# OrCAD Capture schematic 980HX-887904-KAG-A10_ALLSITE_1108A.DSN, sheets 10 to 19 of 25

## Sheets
10 A0001-CONFIG: size A2
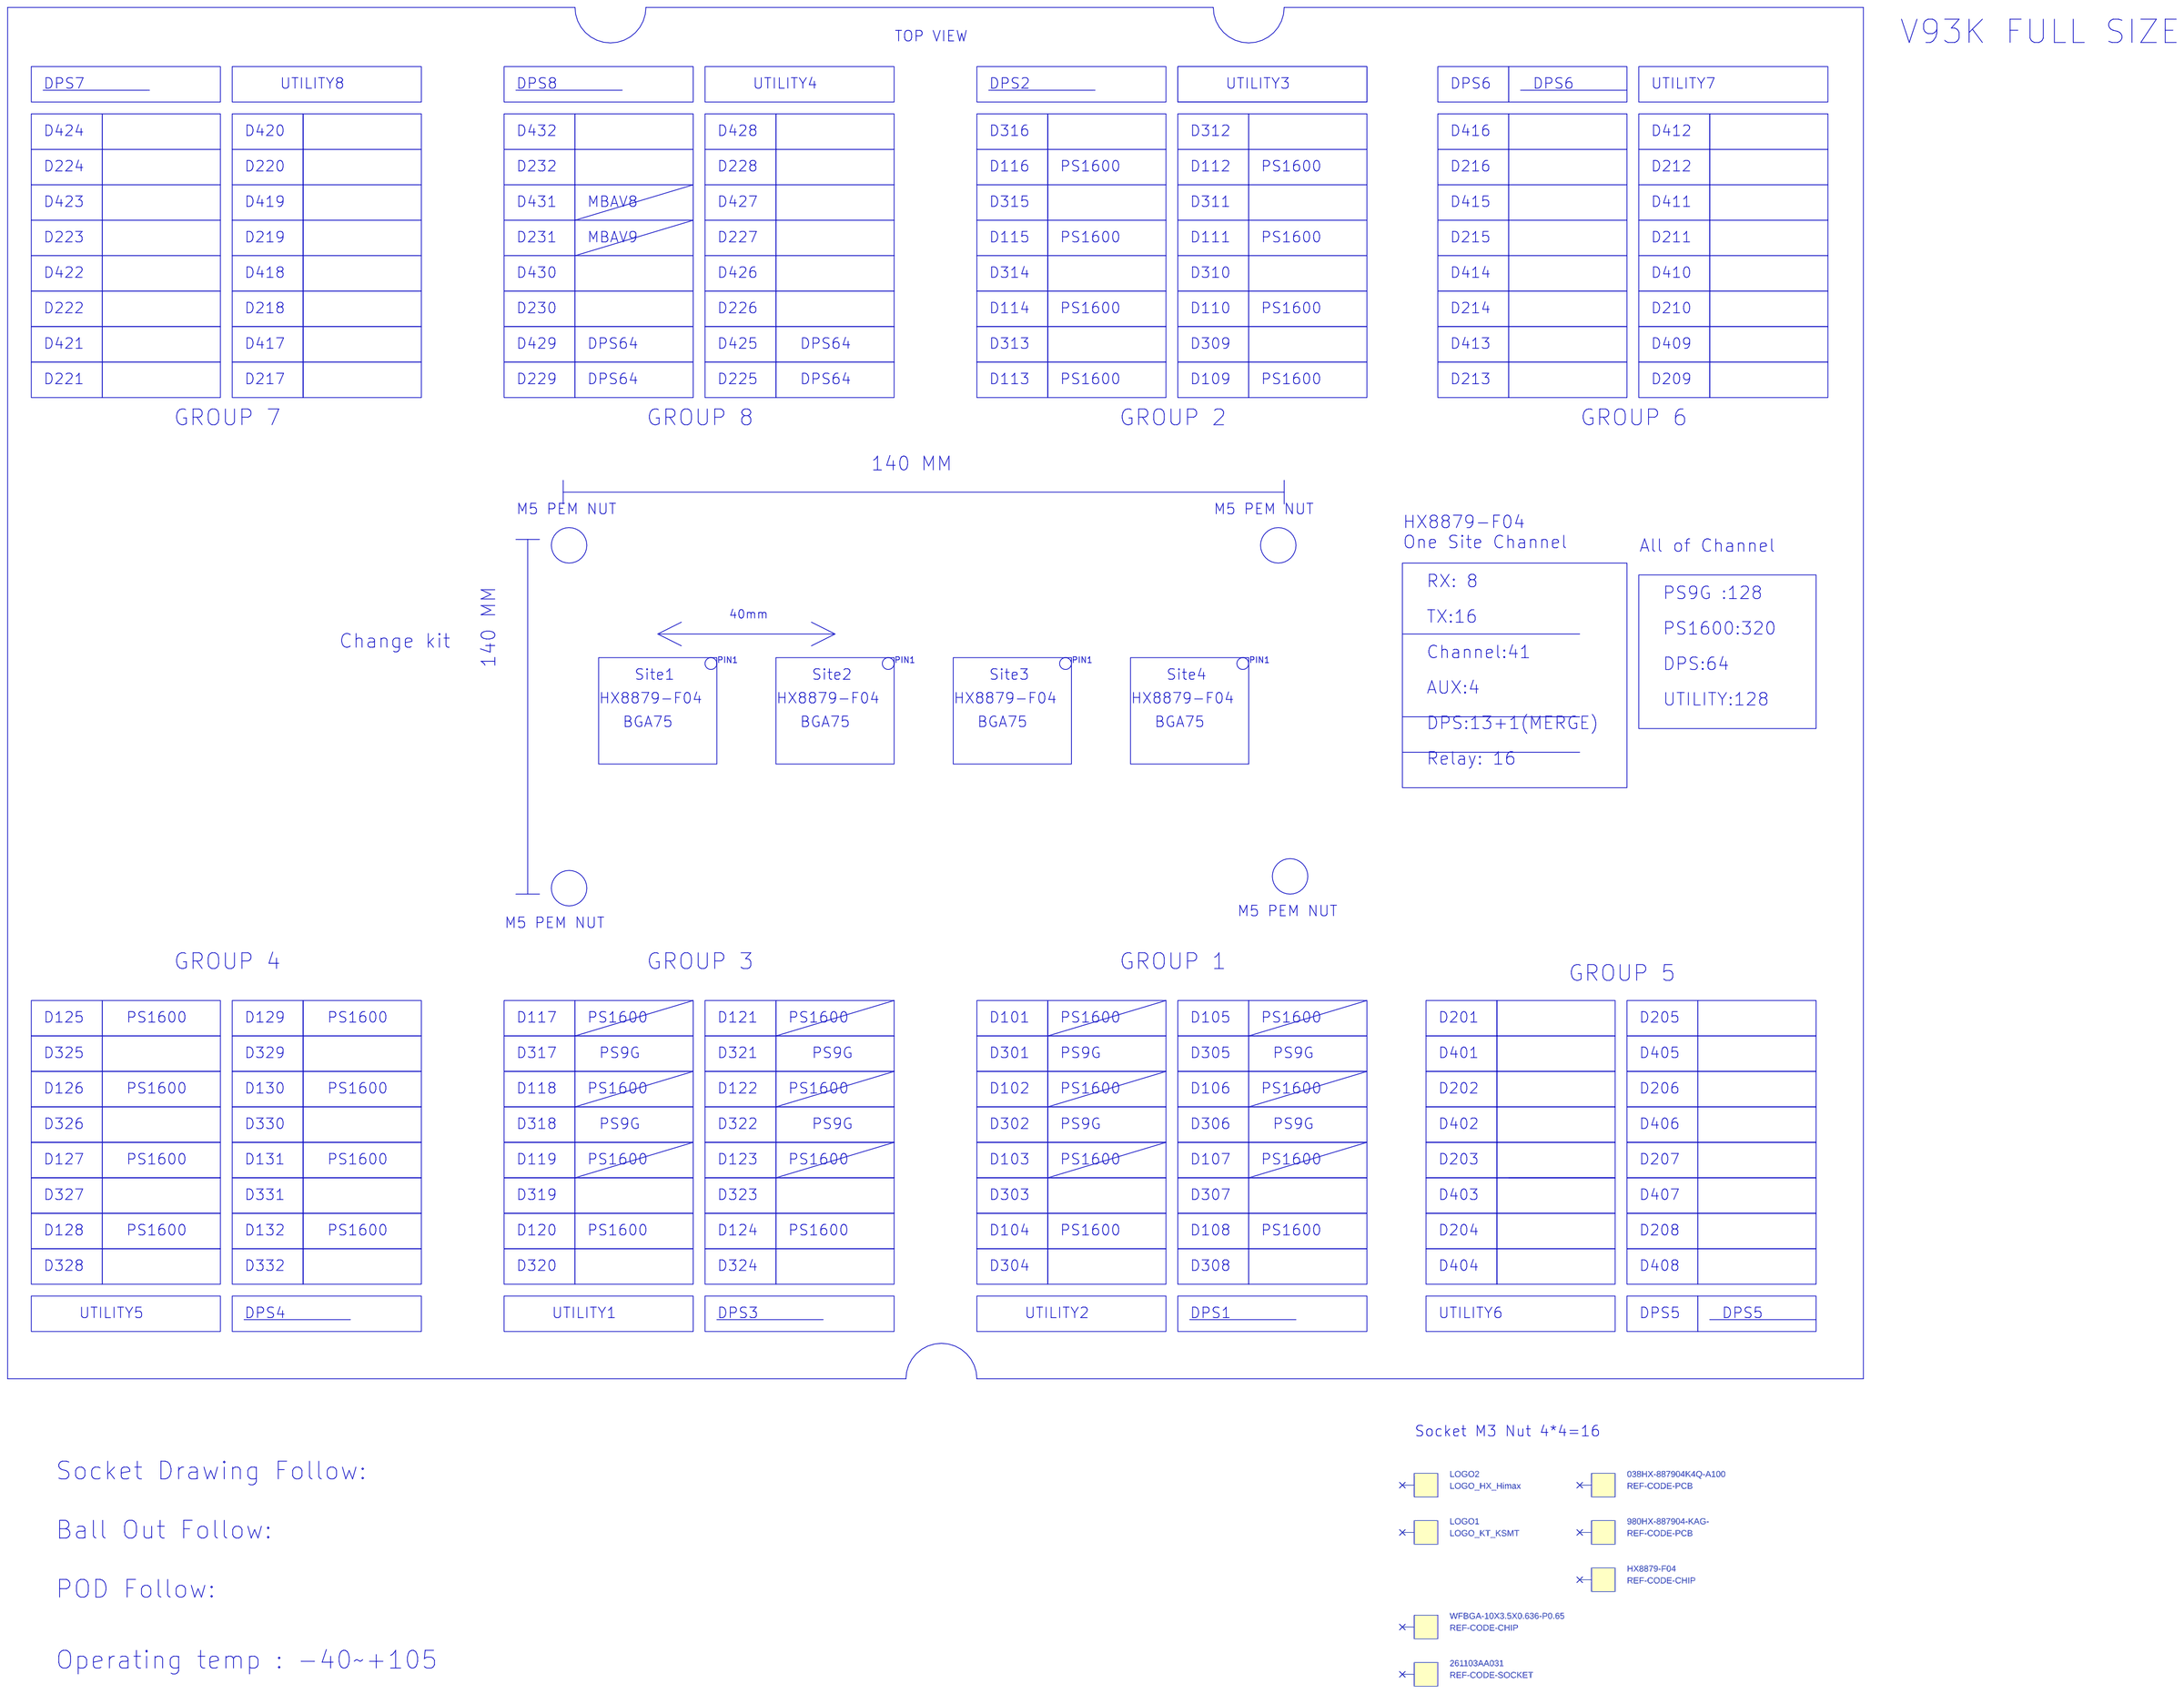
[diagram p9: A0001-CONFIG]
11 A0002-HISTORY
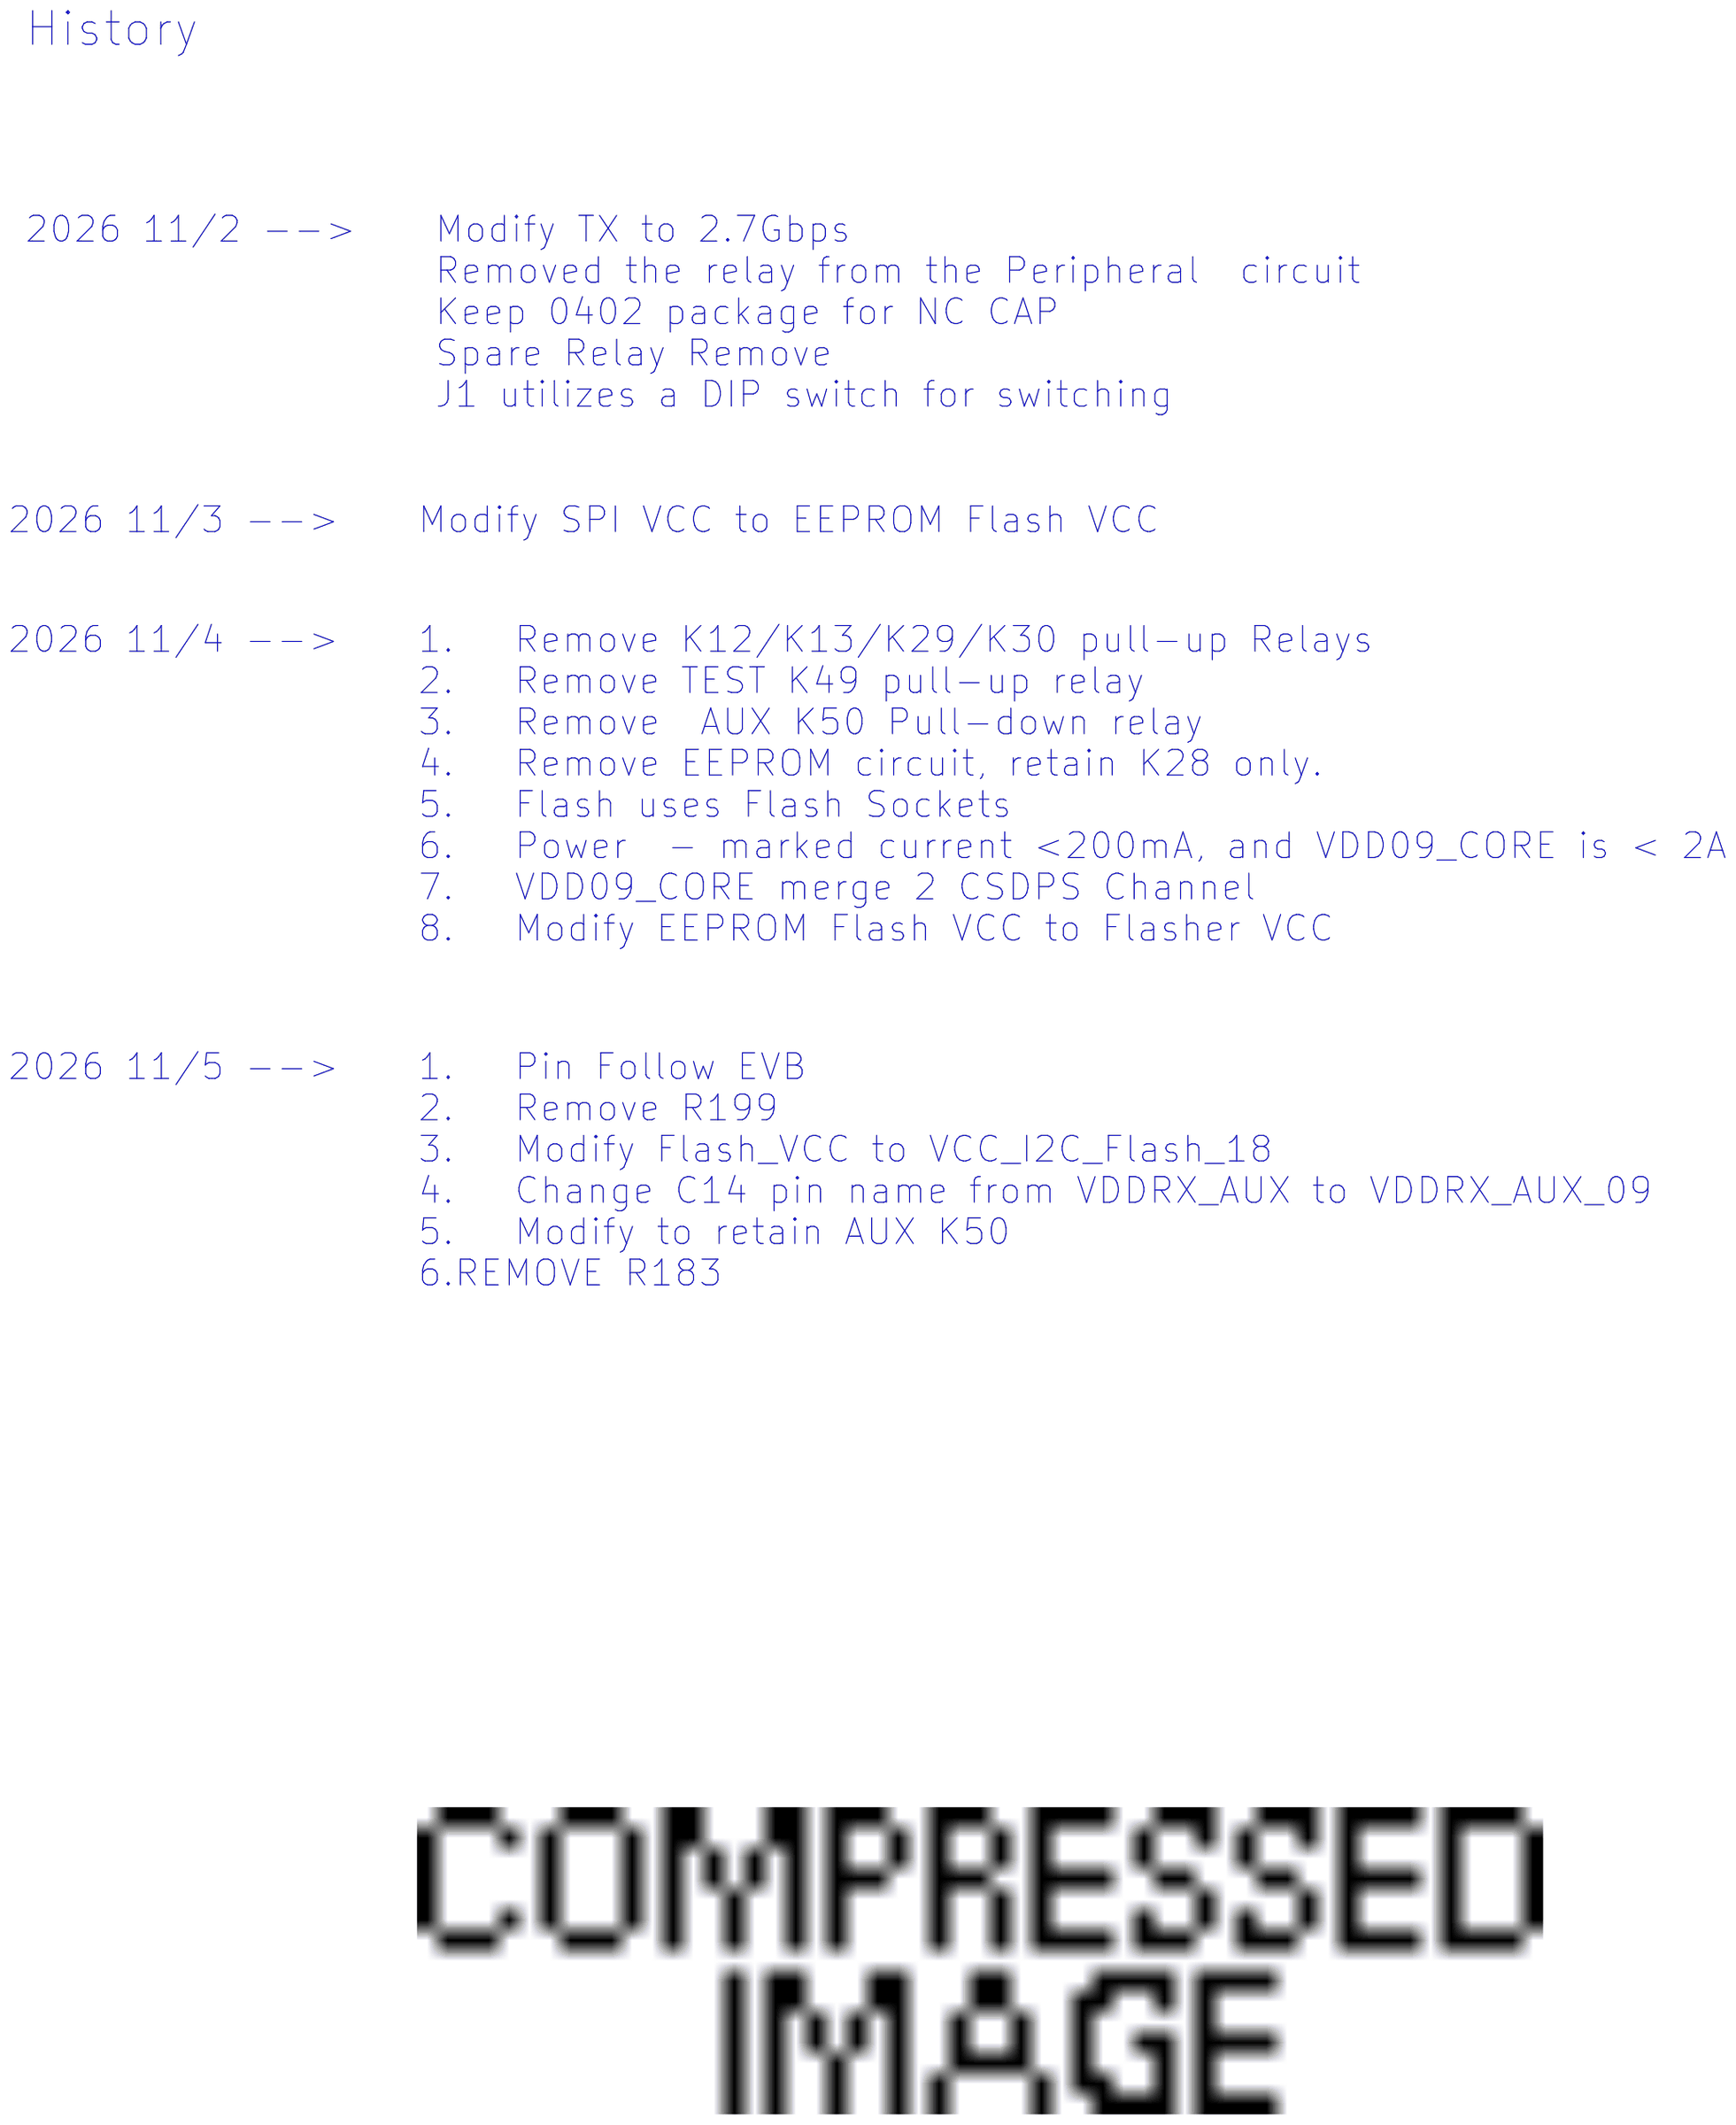
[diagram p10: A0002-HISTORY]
12 P0011_S1_DUT: size A2
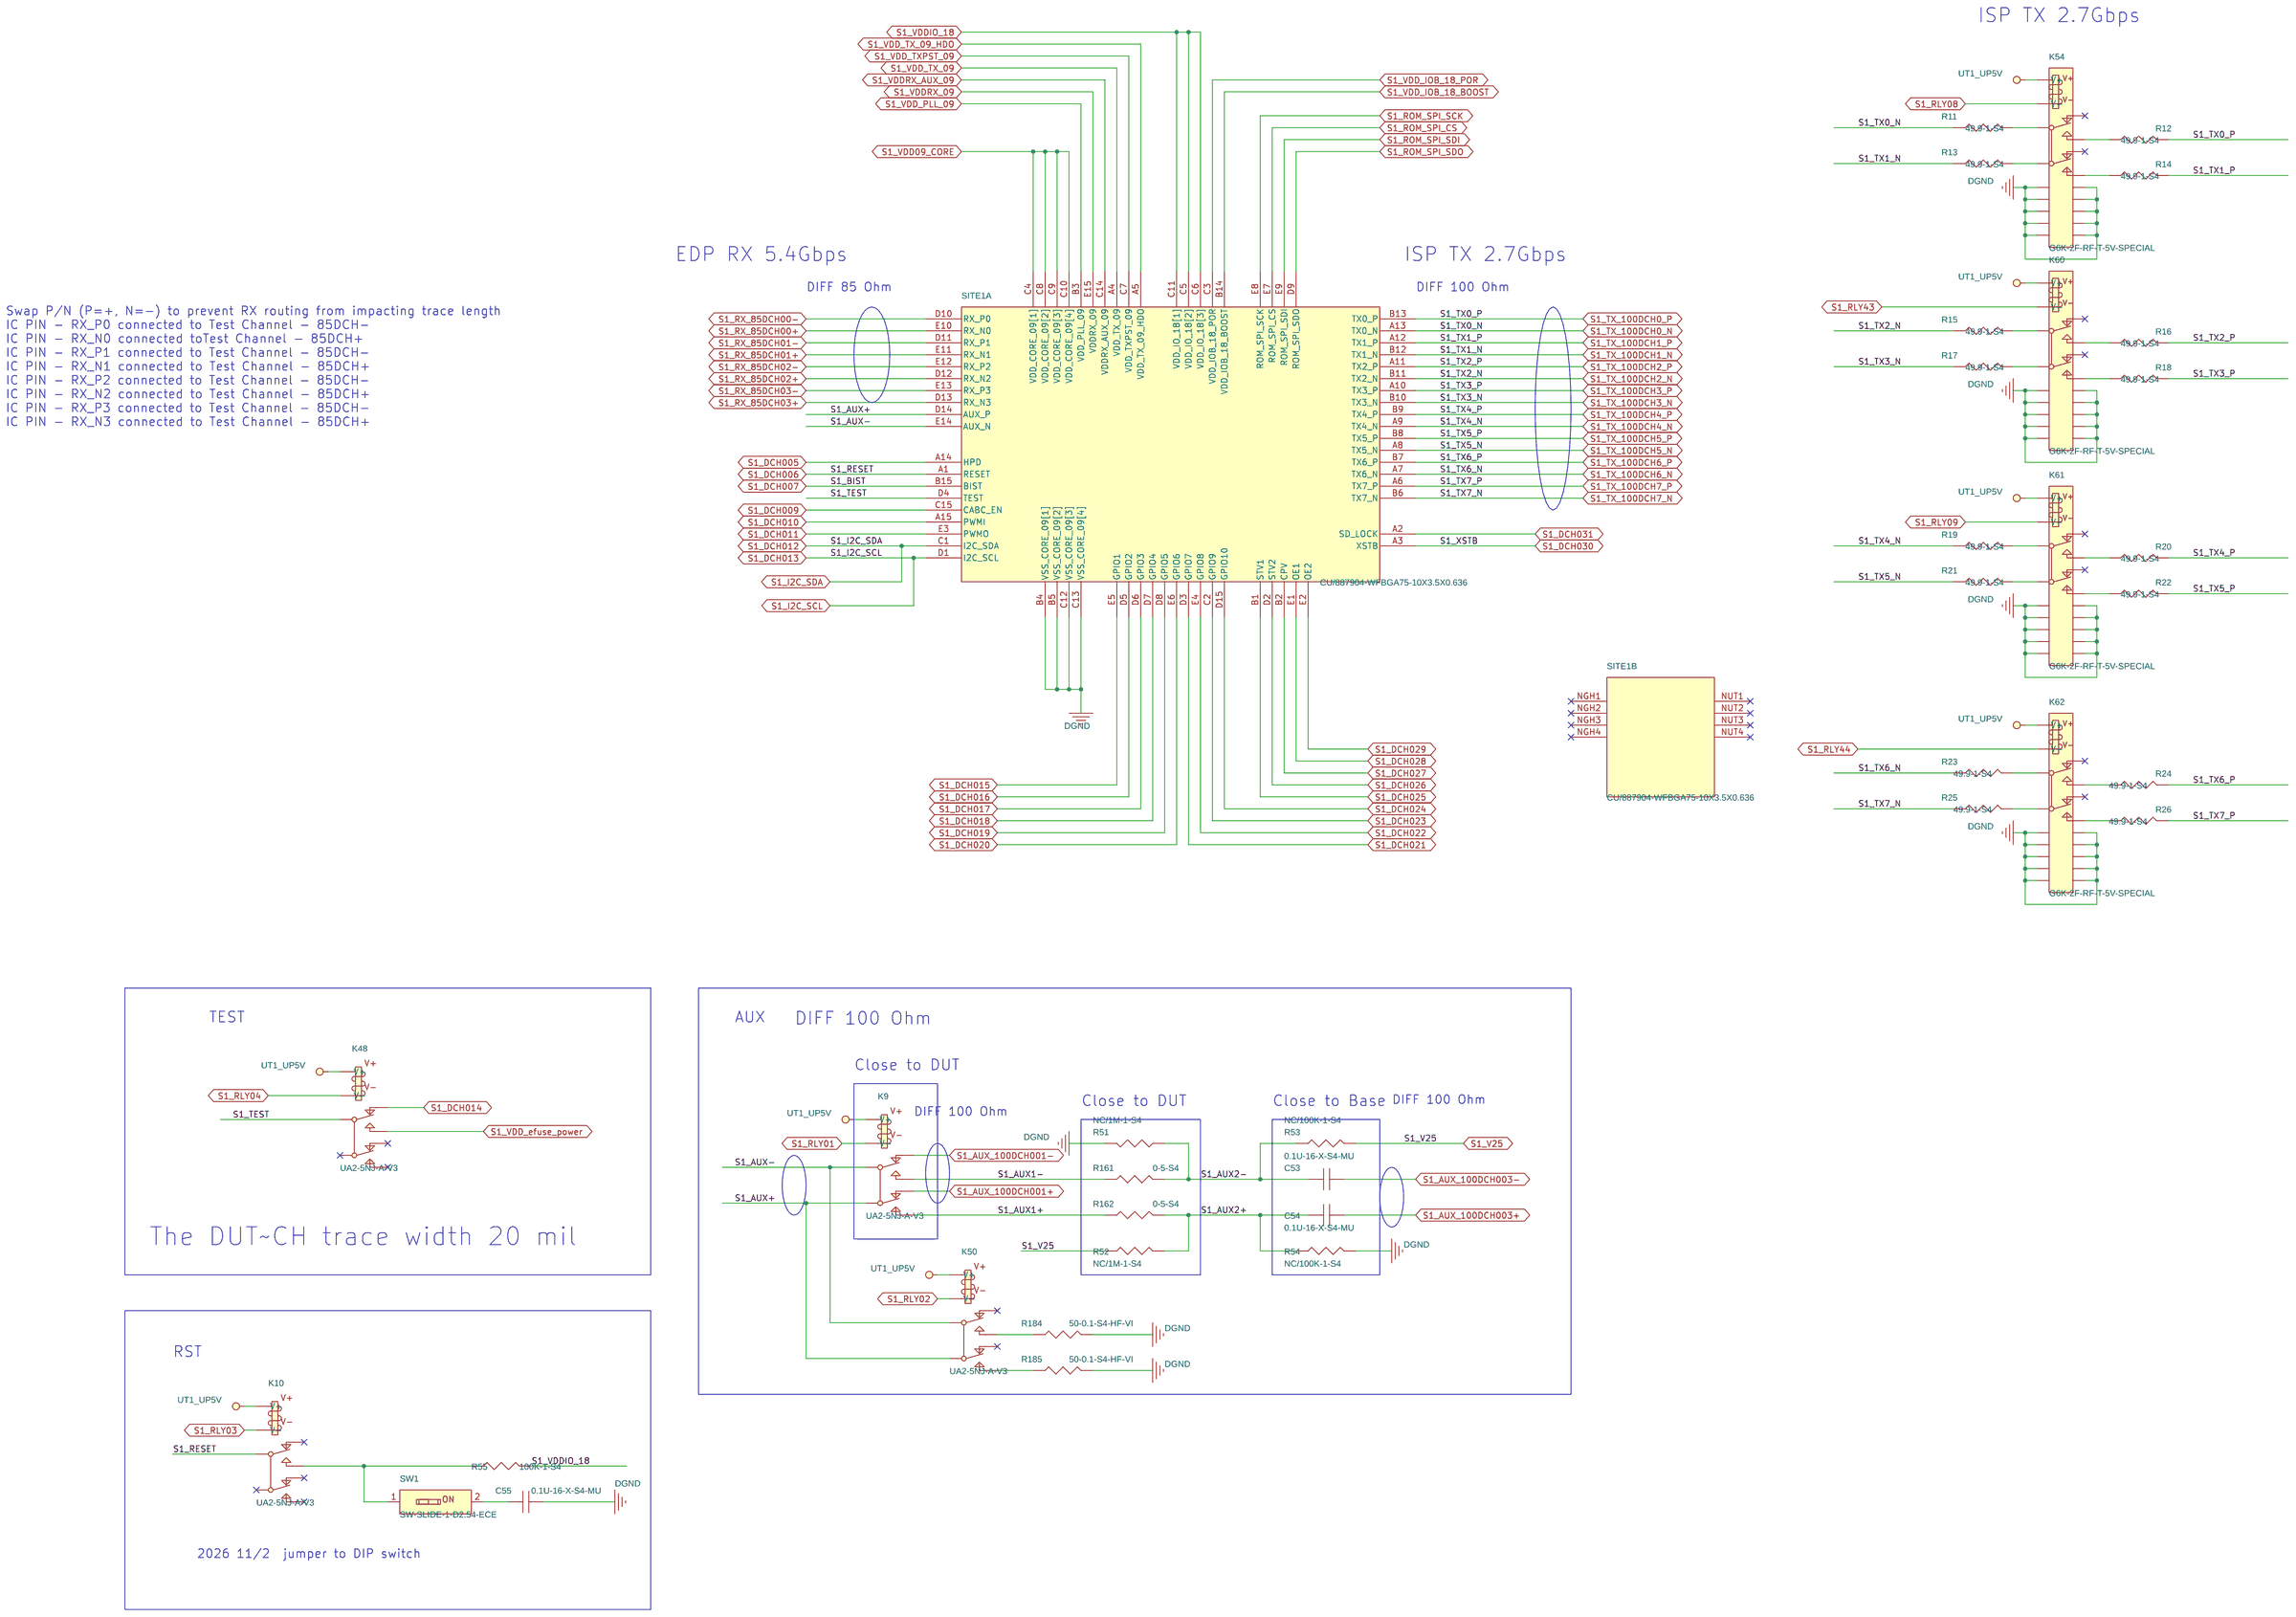
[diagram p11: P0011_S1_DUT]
13 P0012_S1_FLASH_I2C: size A4
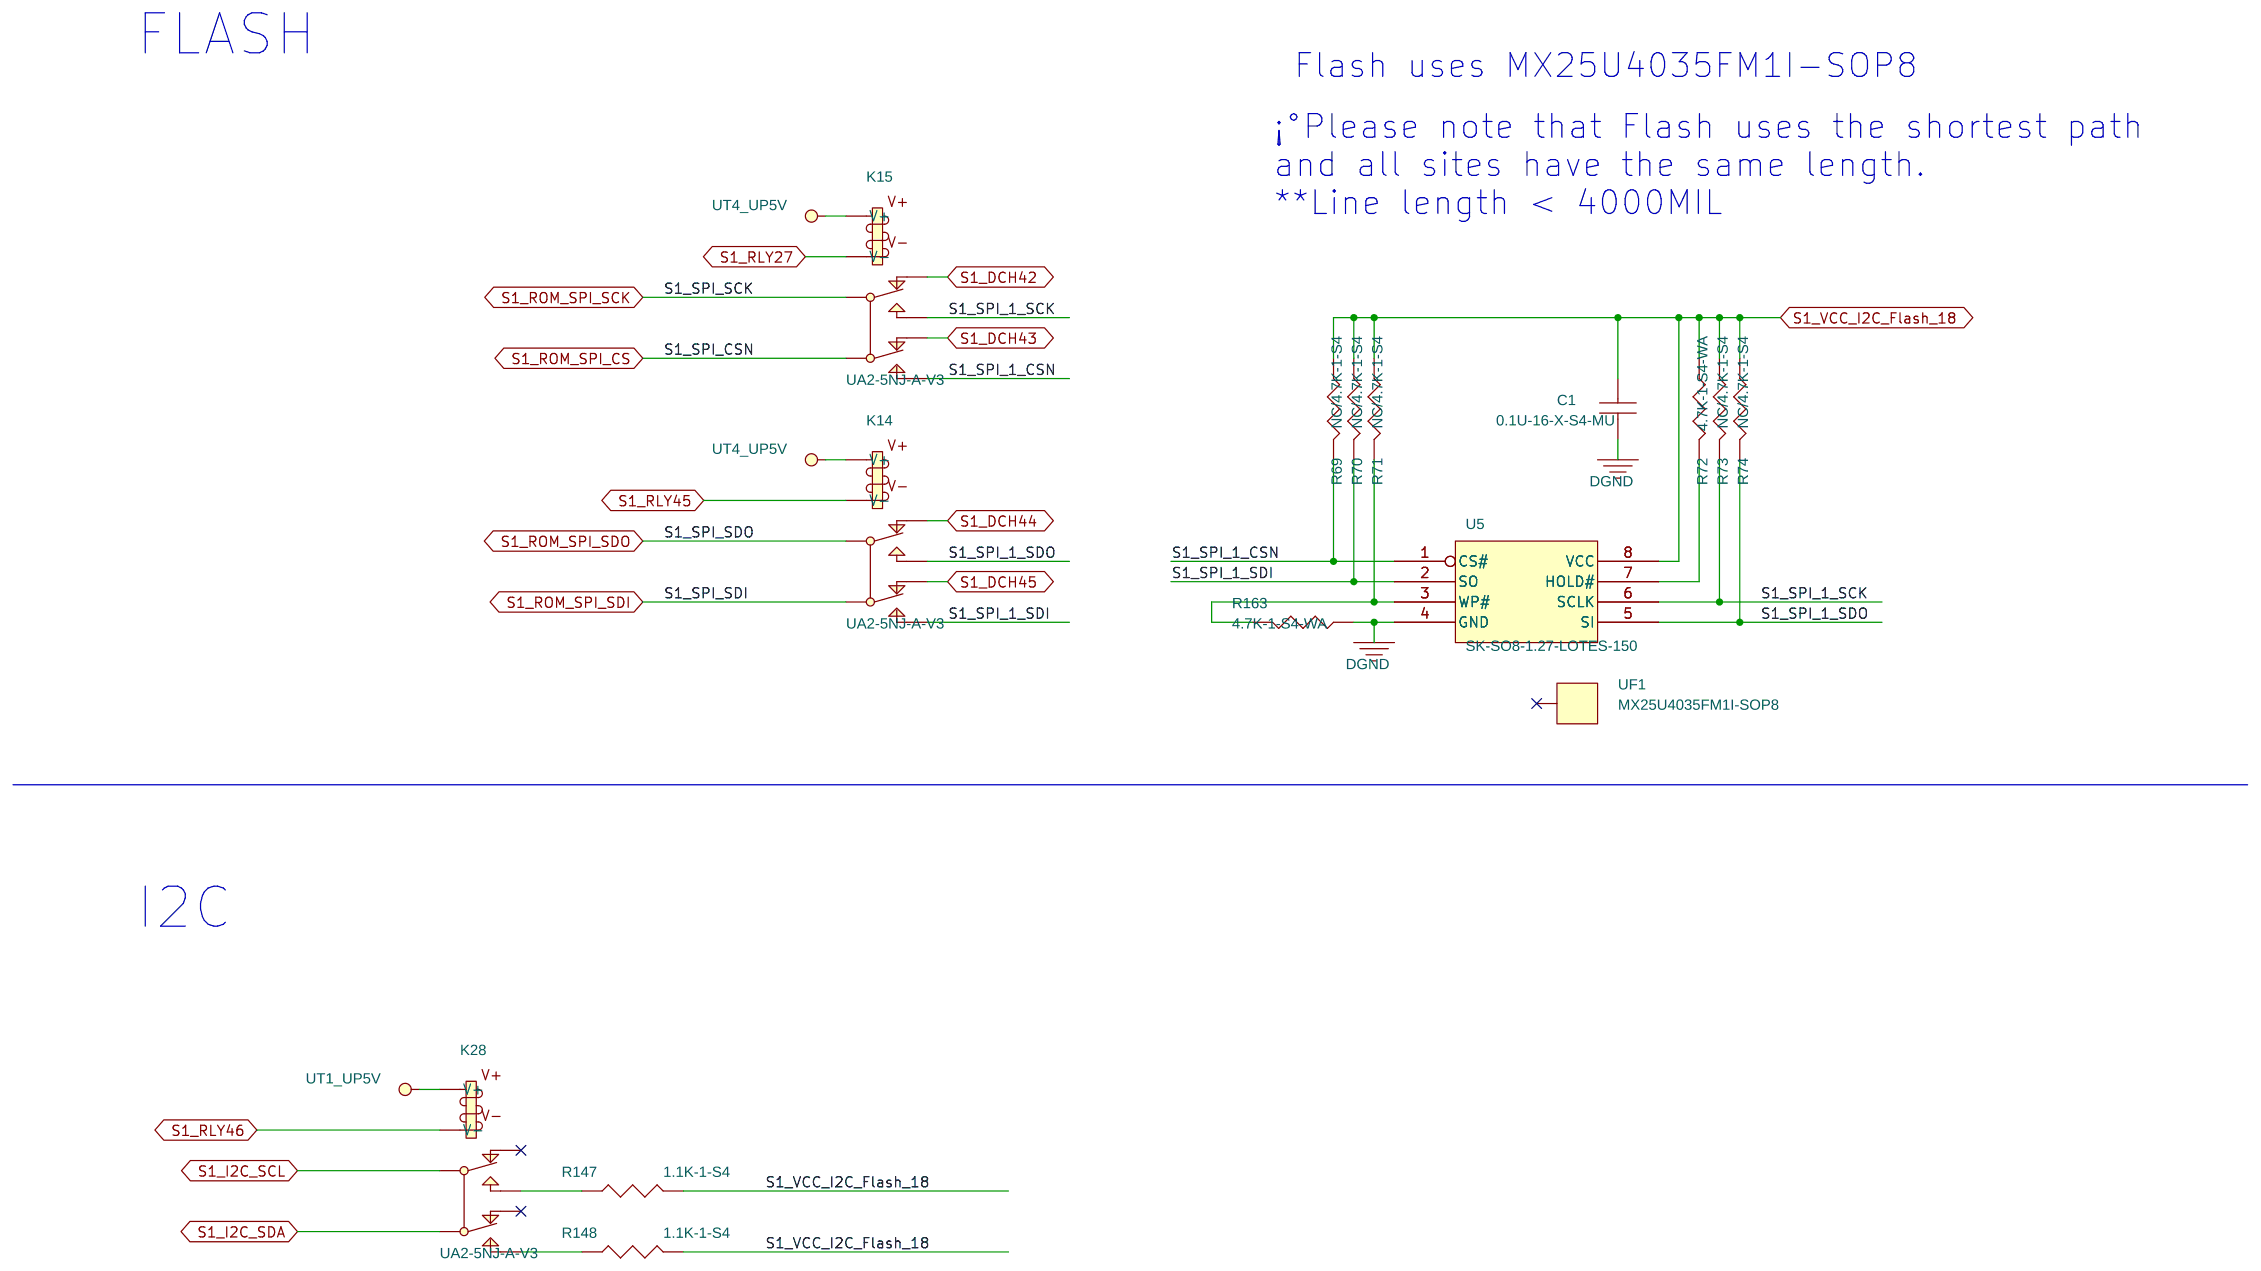
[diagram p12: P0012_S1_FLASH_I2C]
14 P0013_S1_POWER: size A2
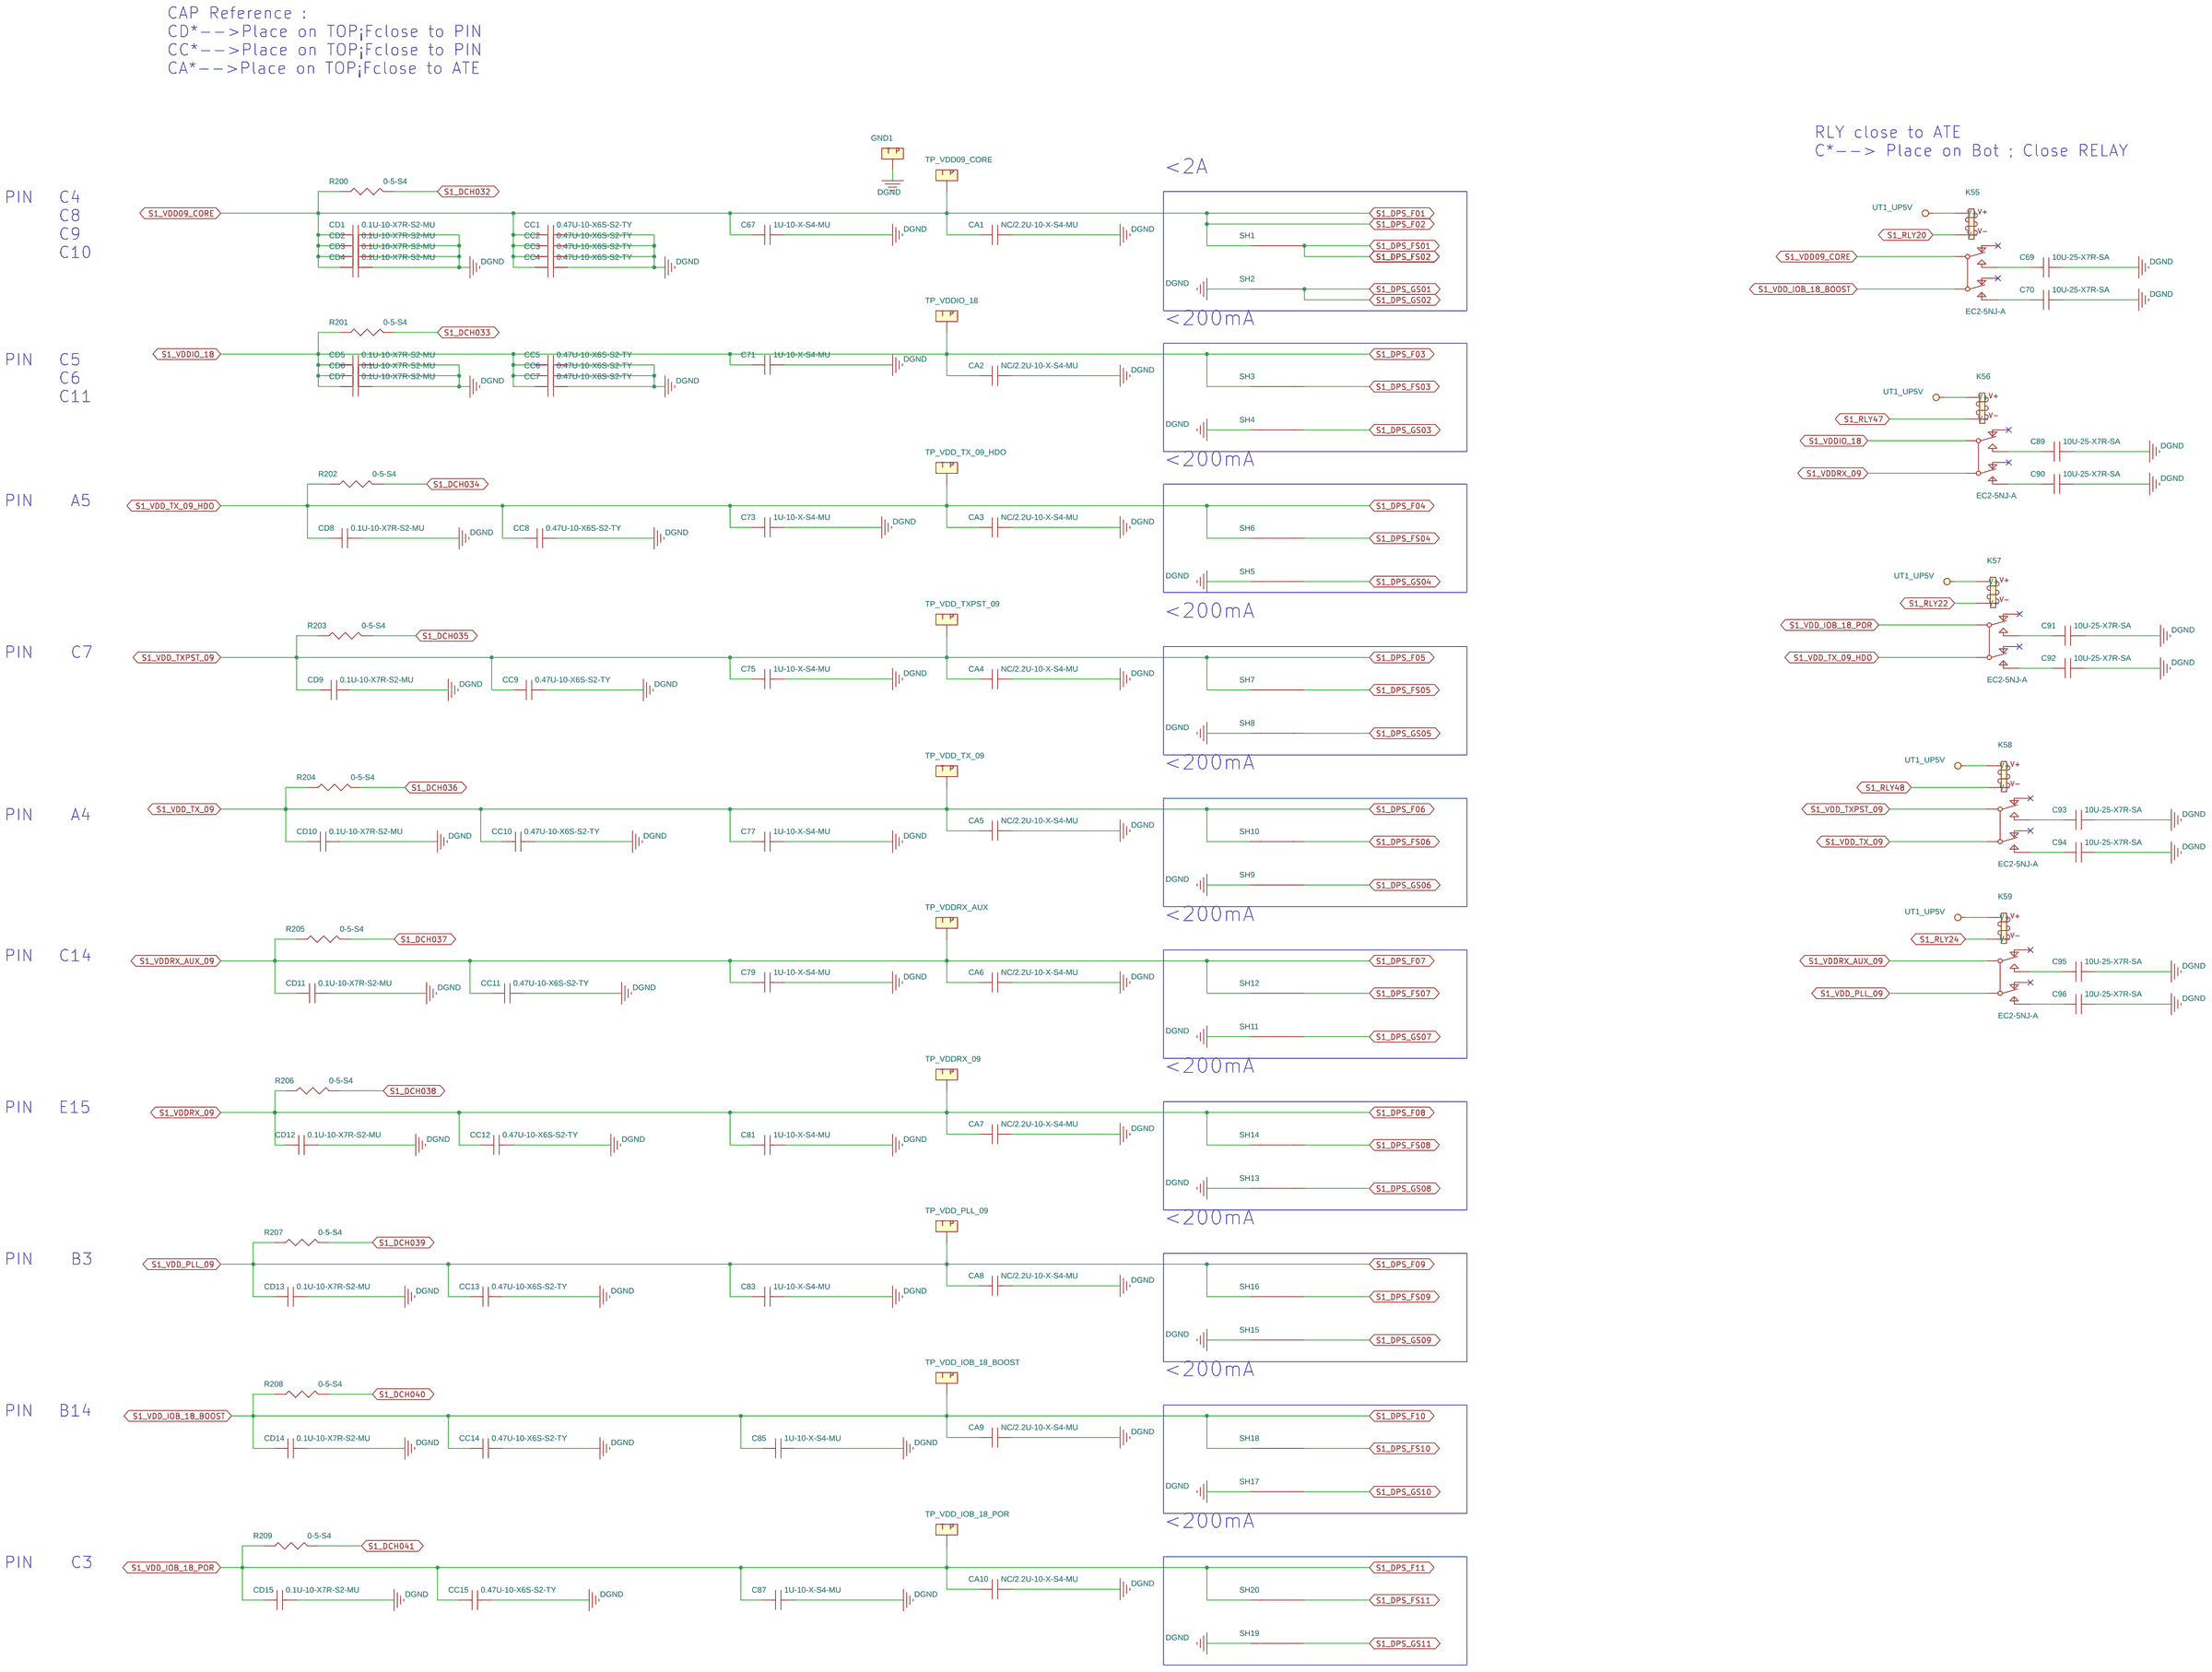
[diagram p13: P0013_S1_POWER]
15 P0014-S1_PWR-OUT: size A4
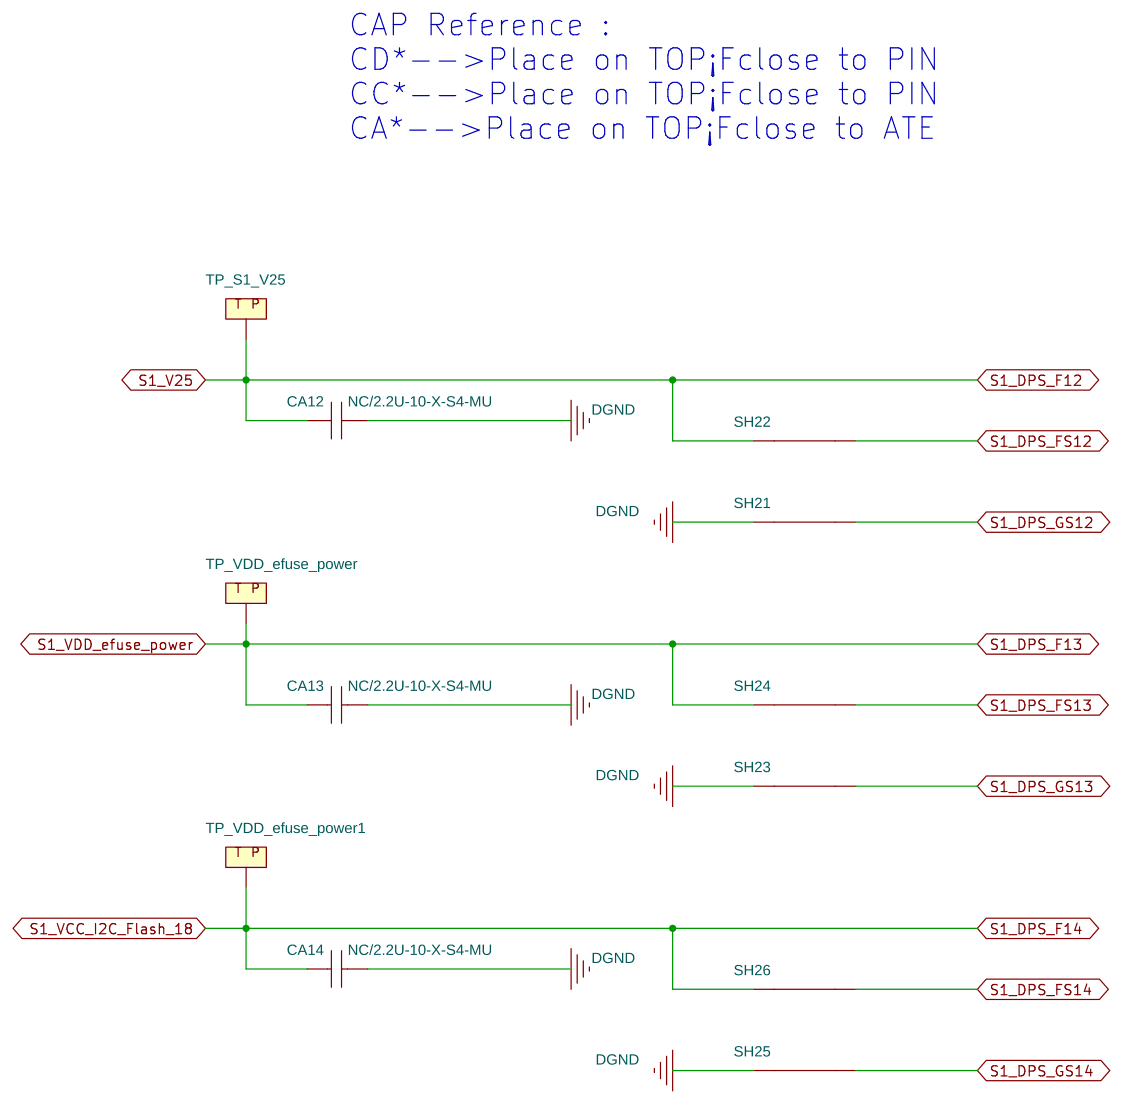
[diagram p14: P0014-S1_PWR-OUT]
16 S9999_MISC: size A3
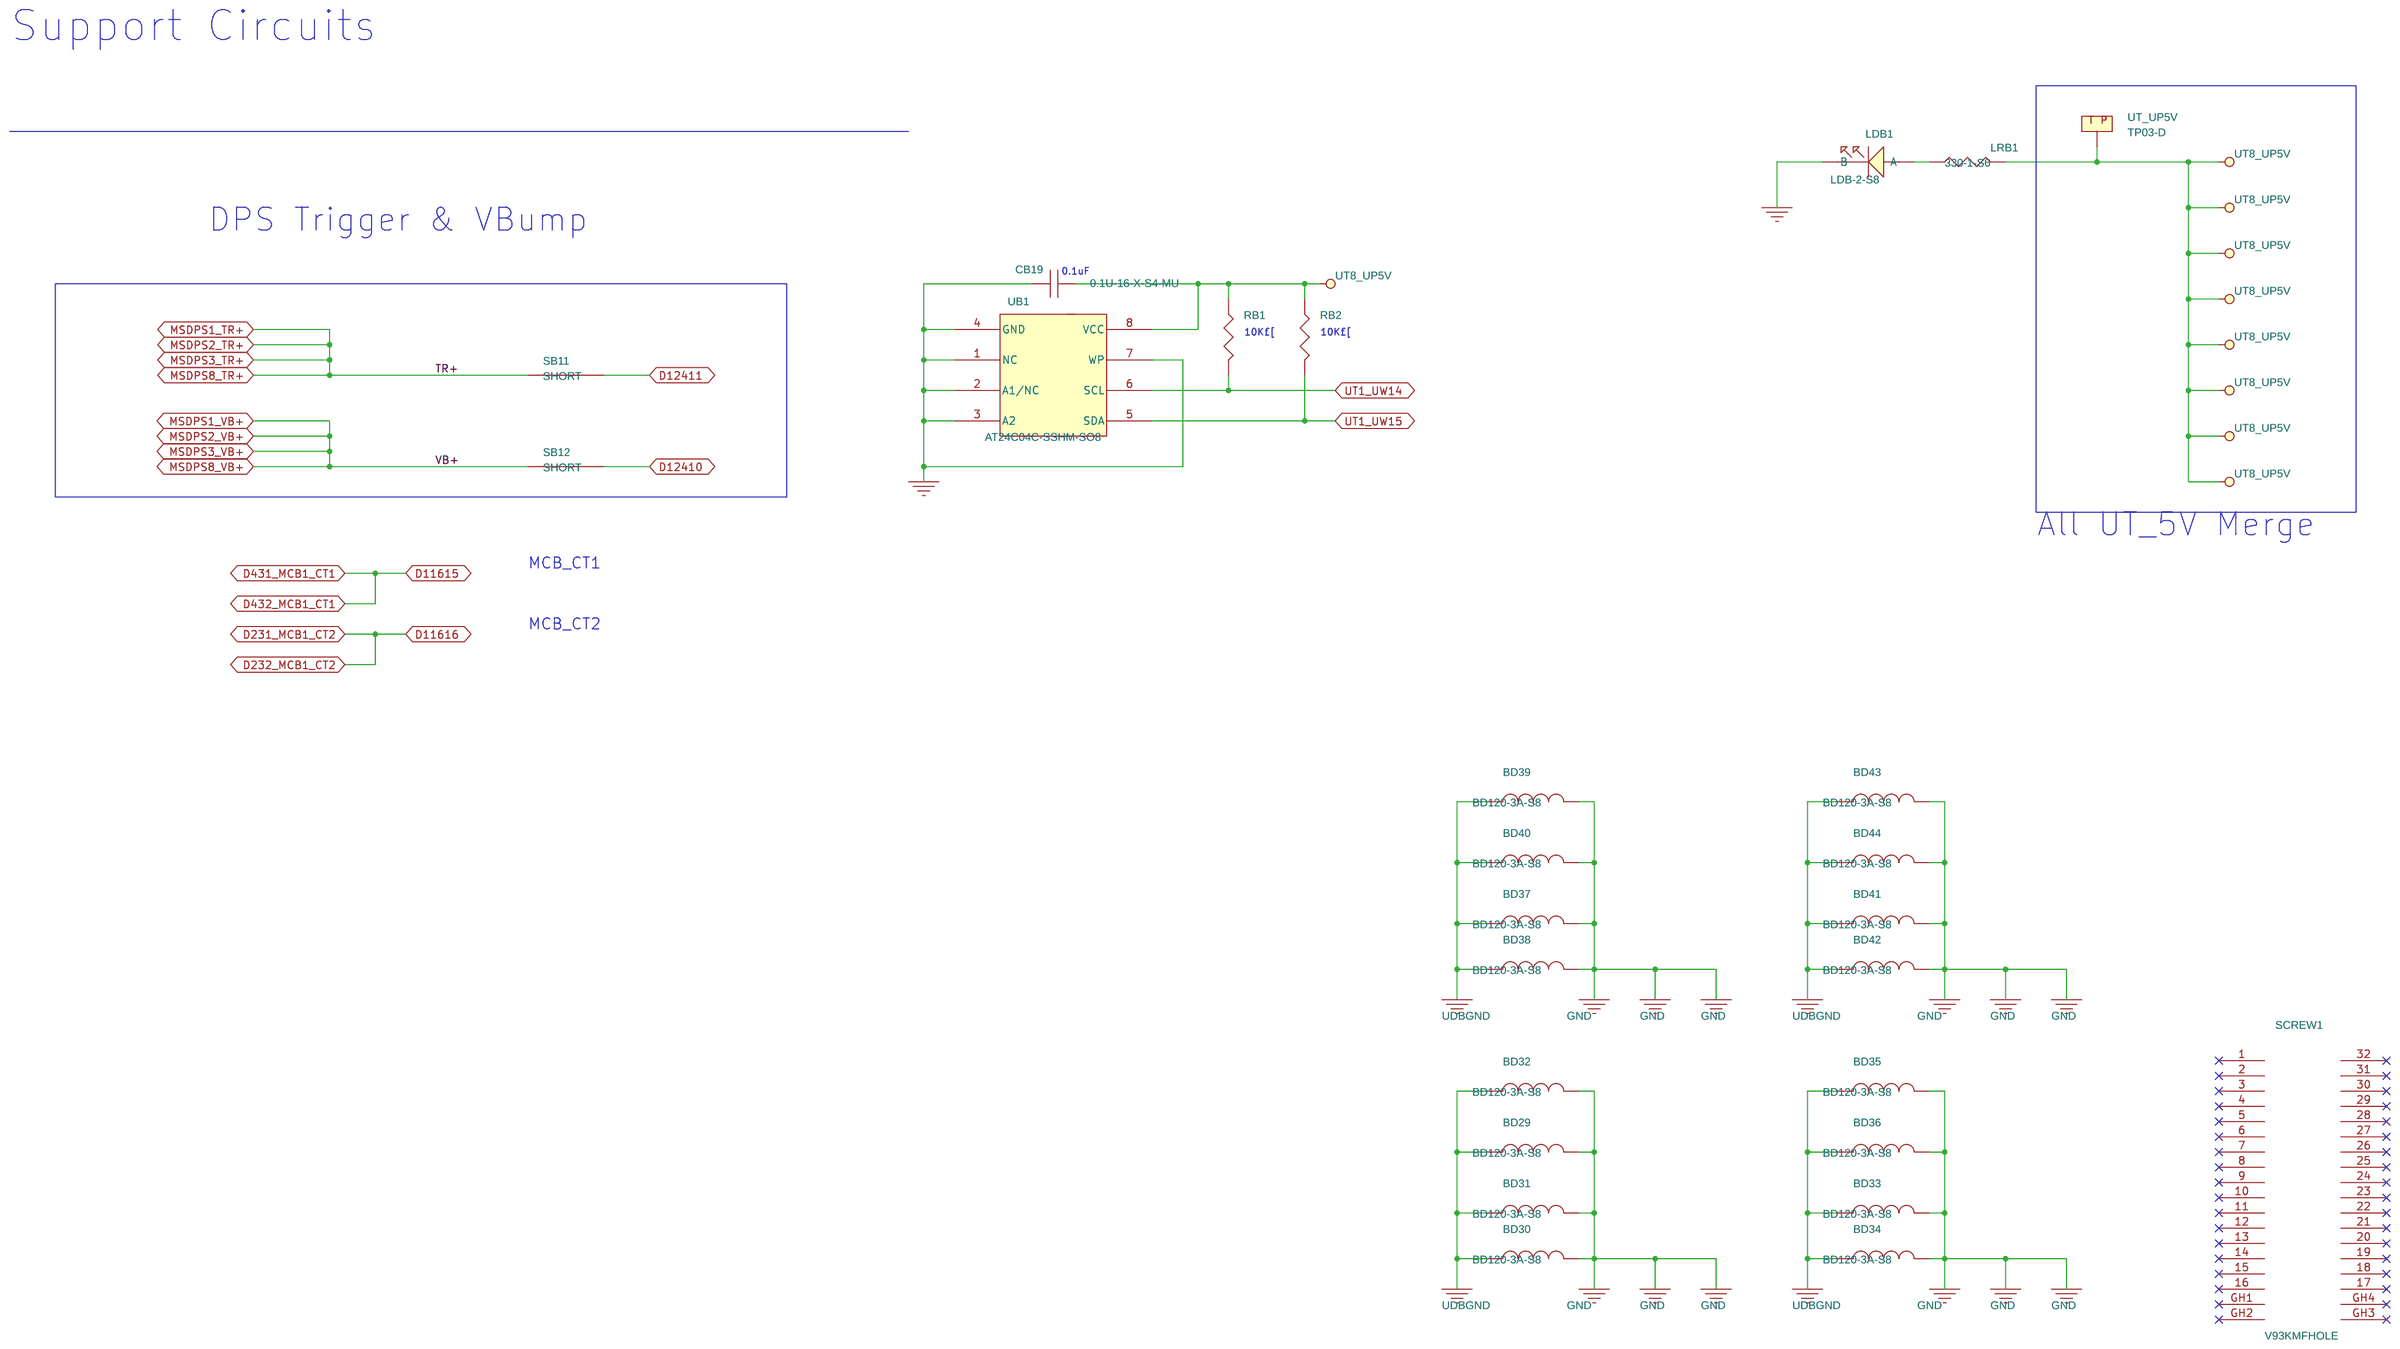
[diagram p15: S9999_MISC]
17 T01.GROUP1.U2: size D
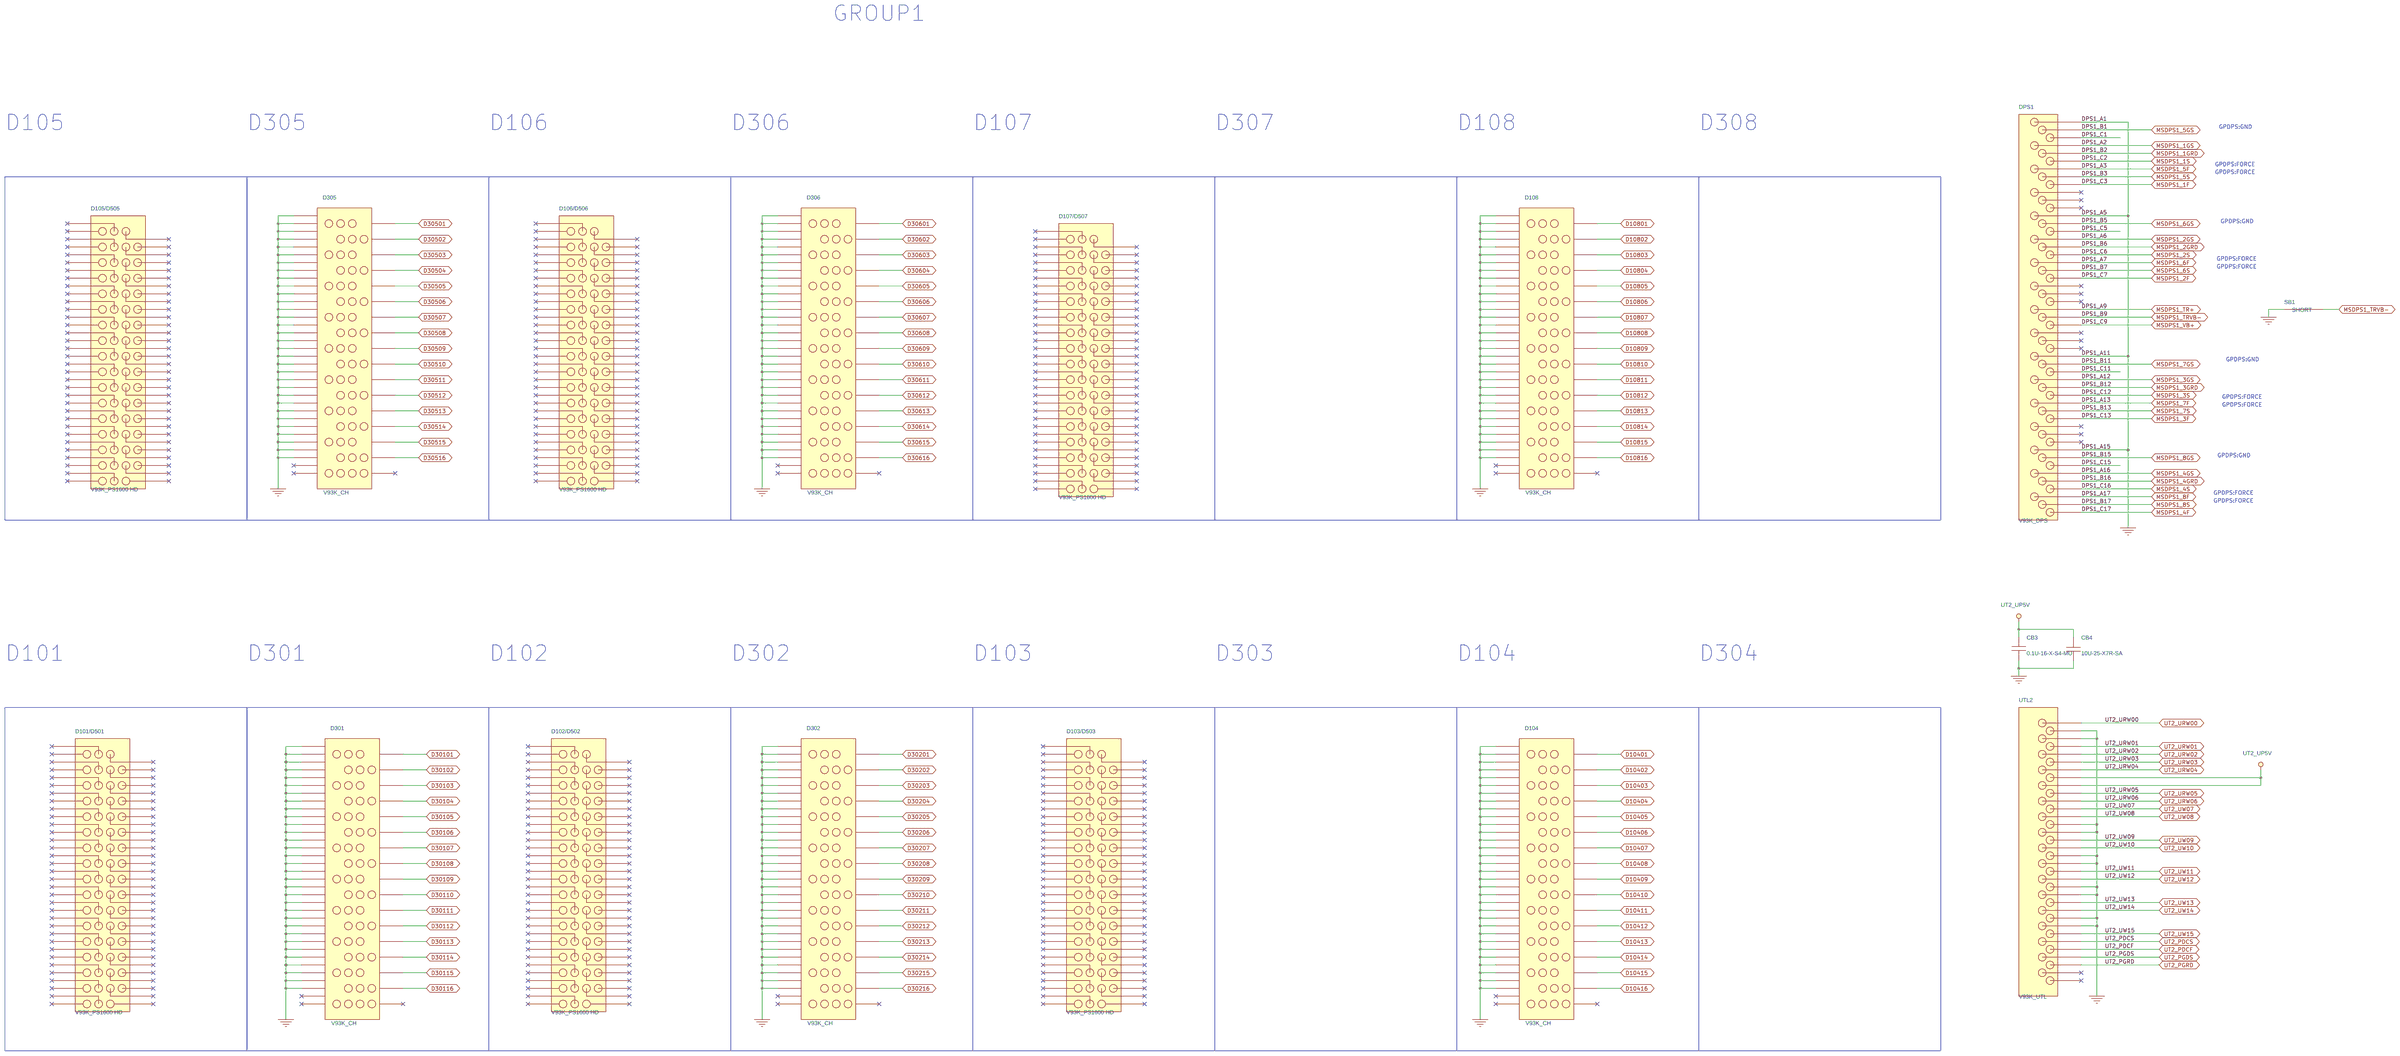
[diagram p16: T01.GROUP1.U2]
18 T02.GROUP2.U3: size D
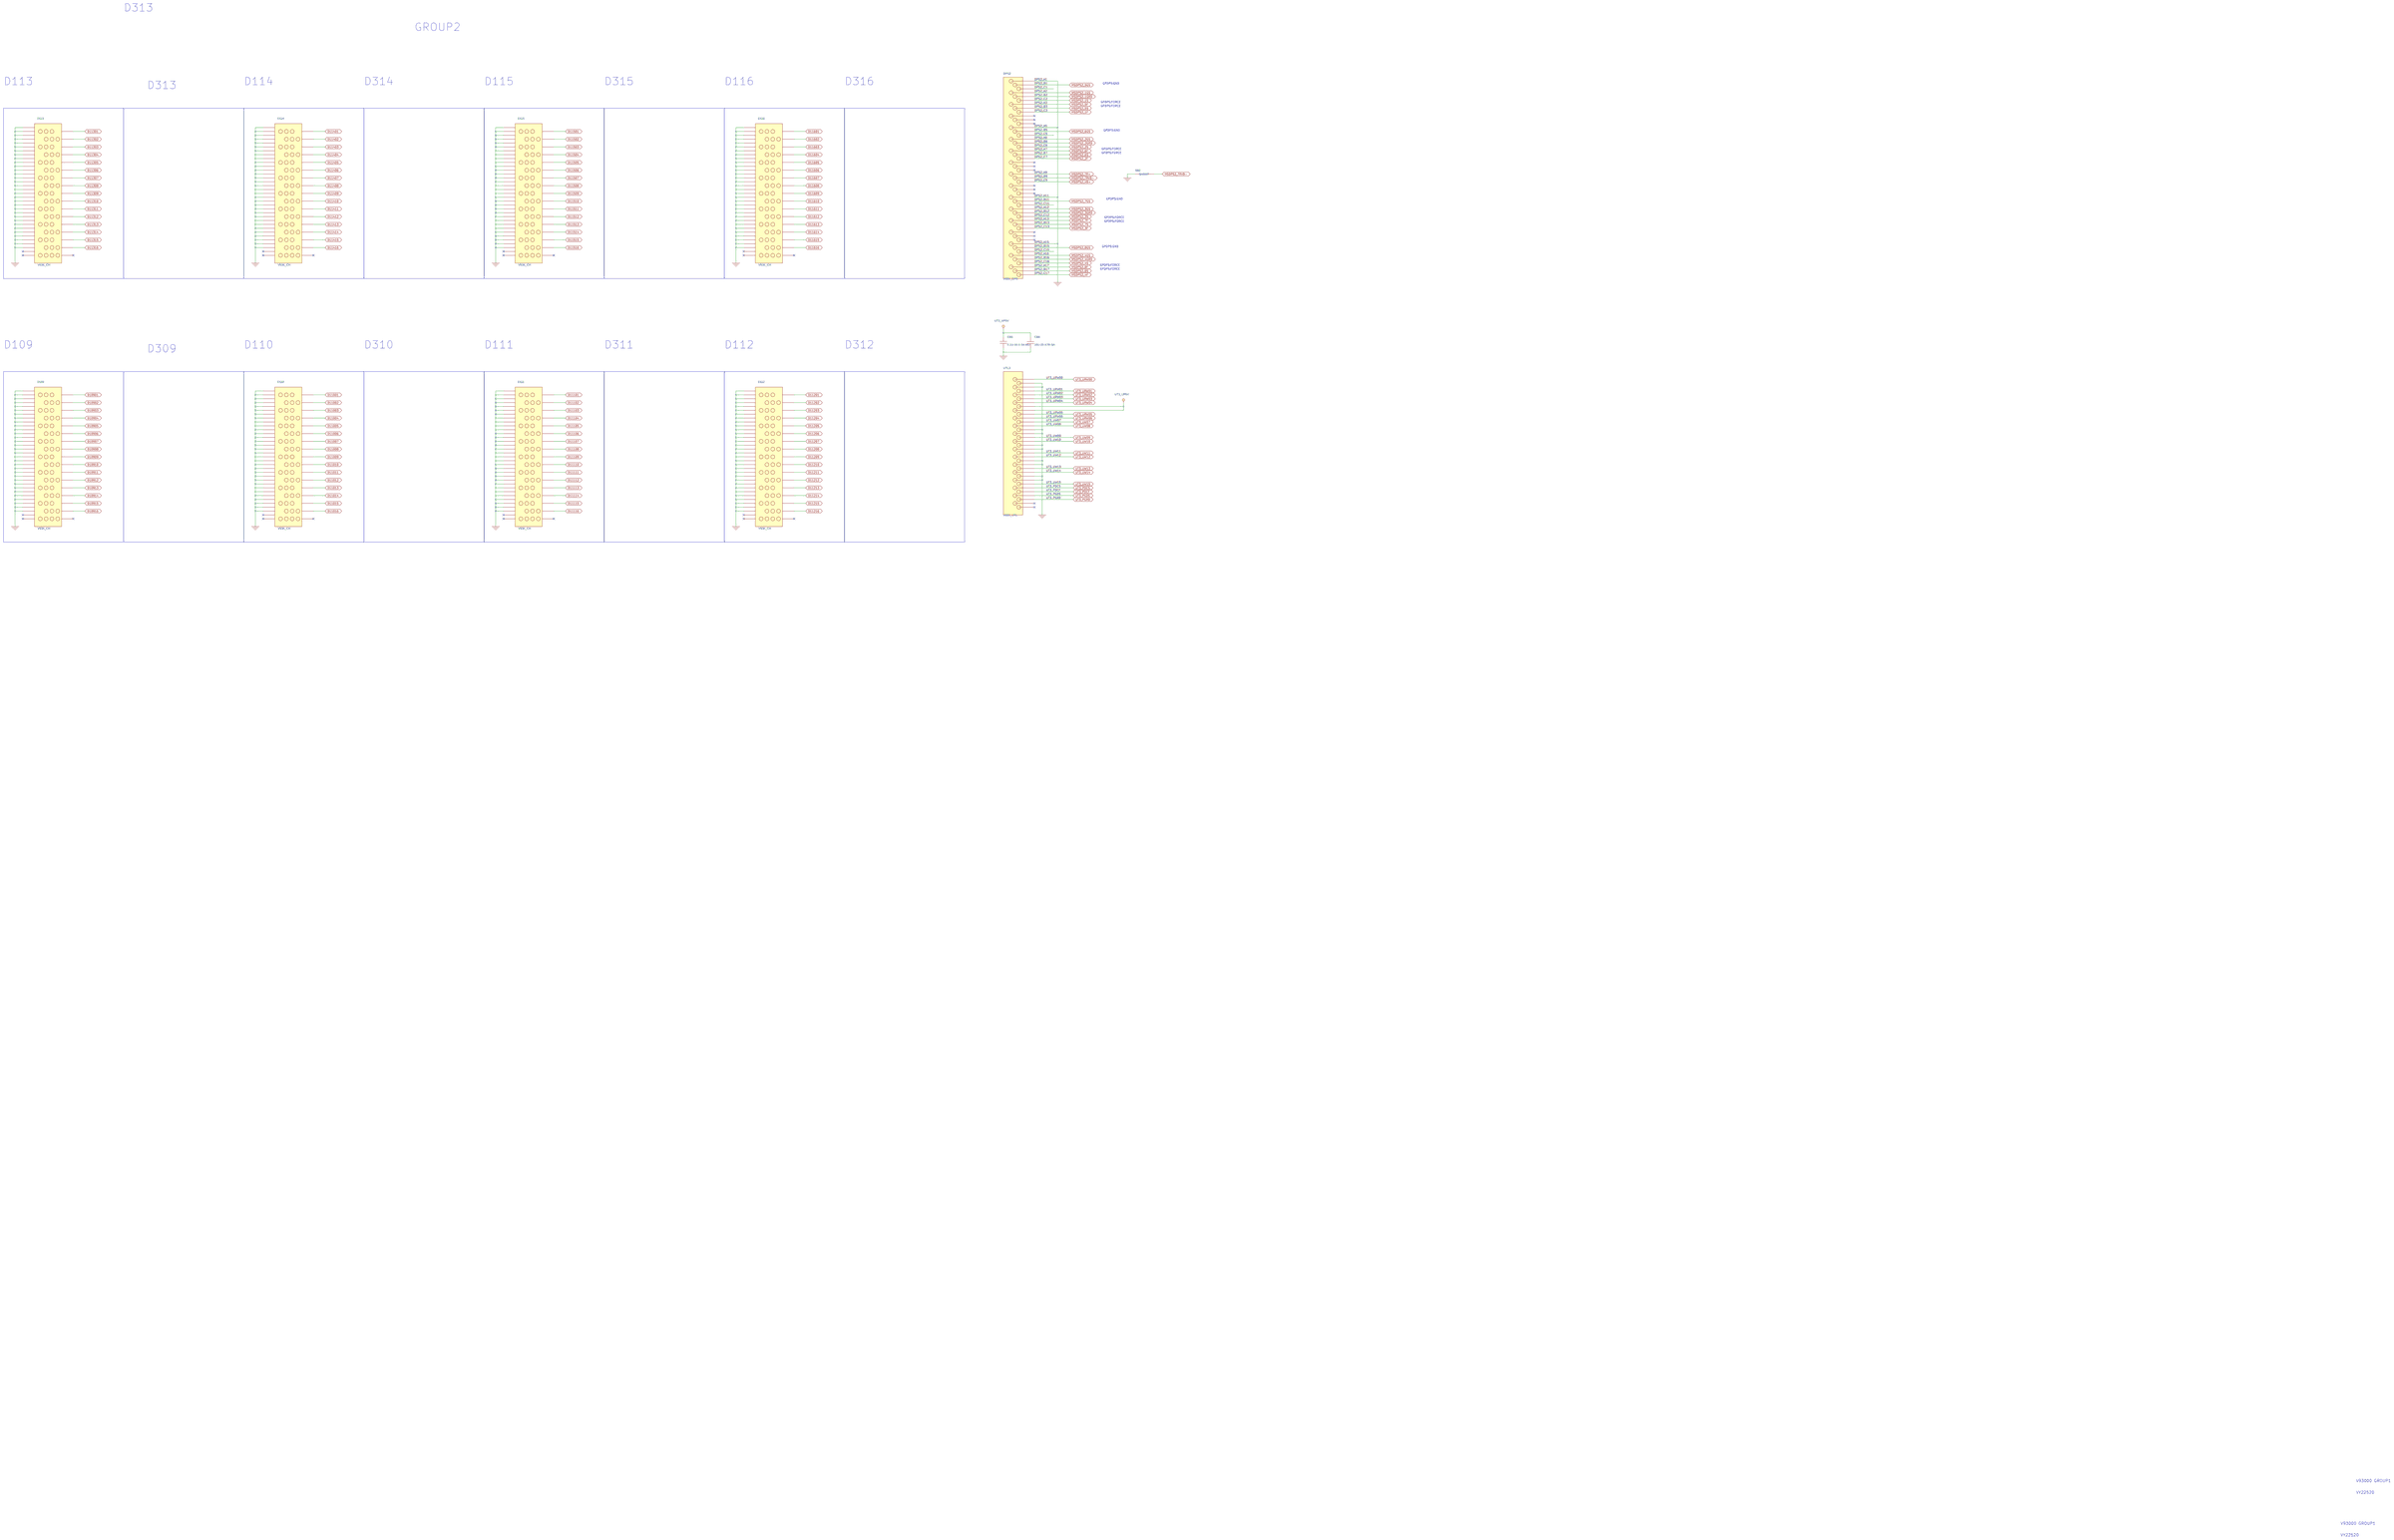
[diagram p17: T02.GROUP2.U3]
19 T03.GROUP3.U1: size D
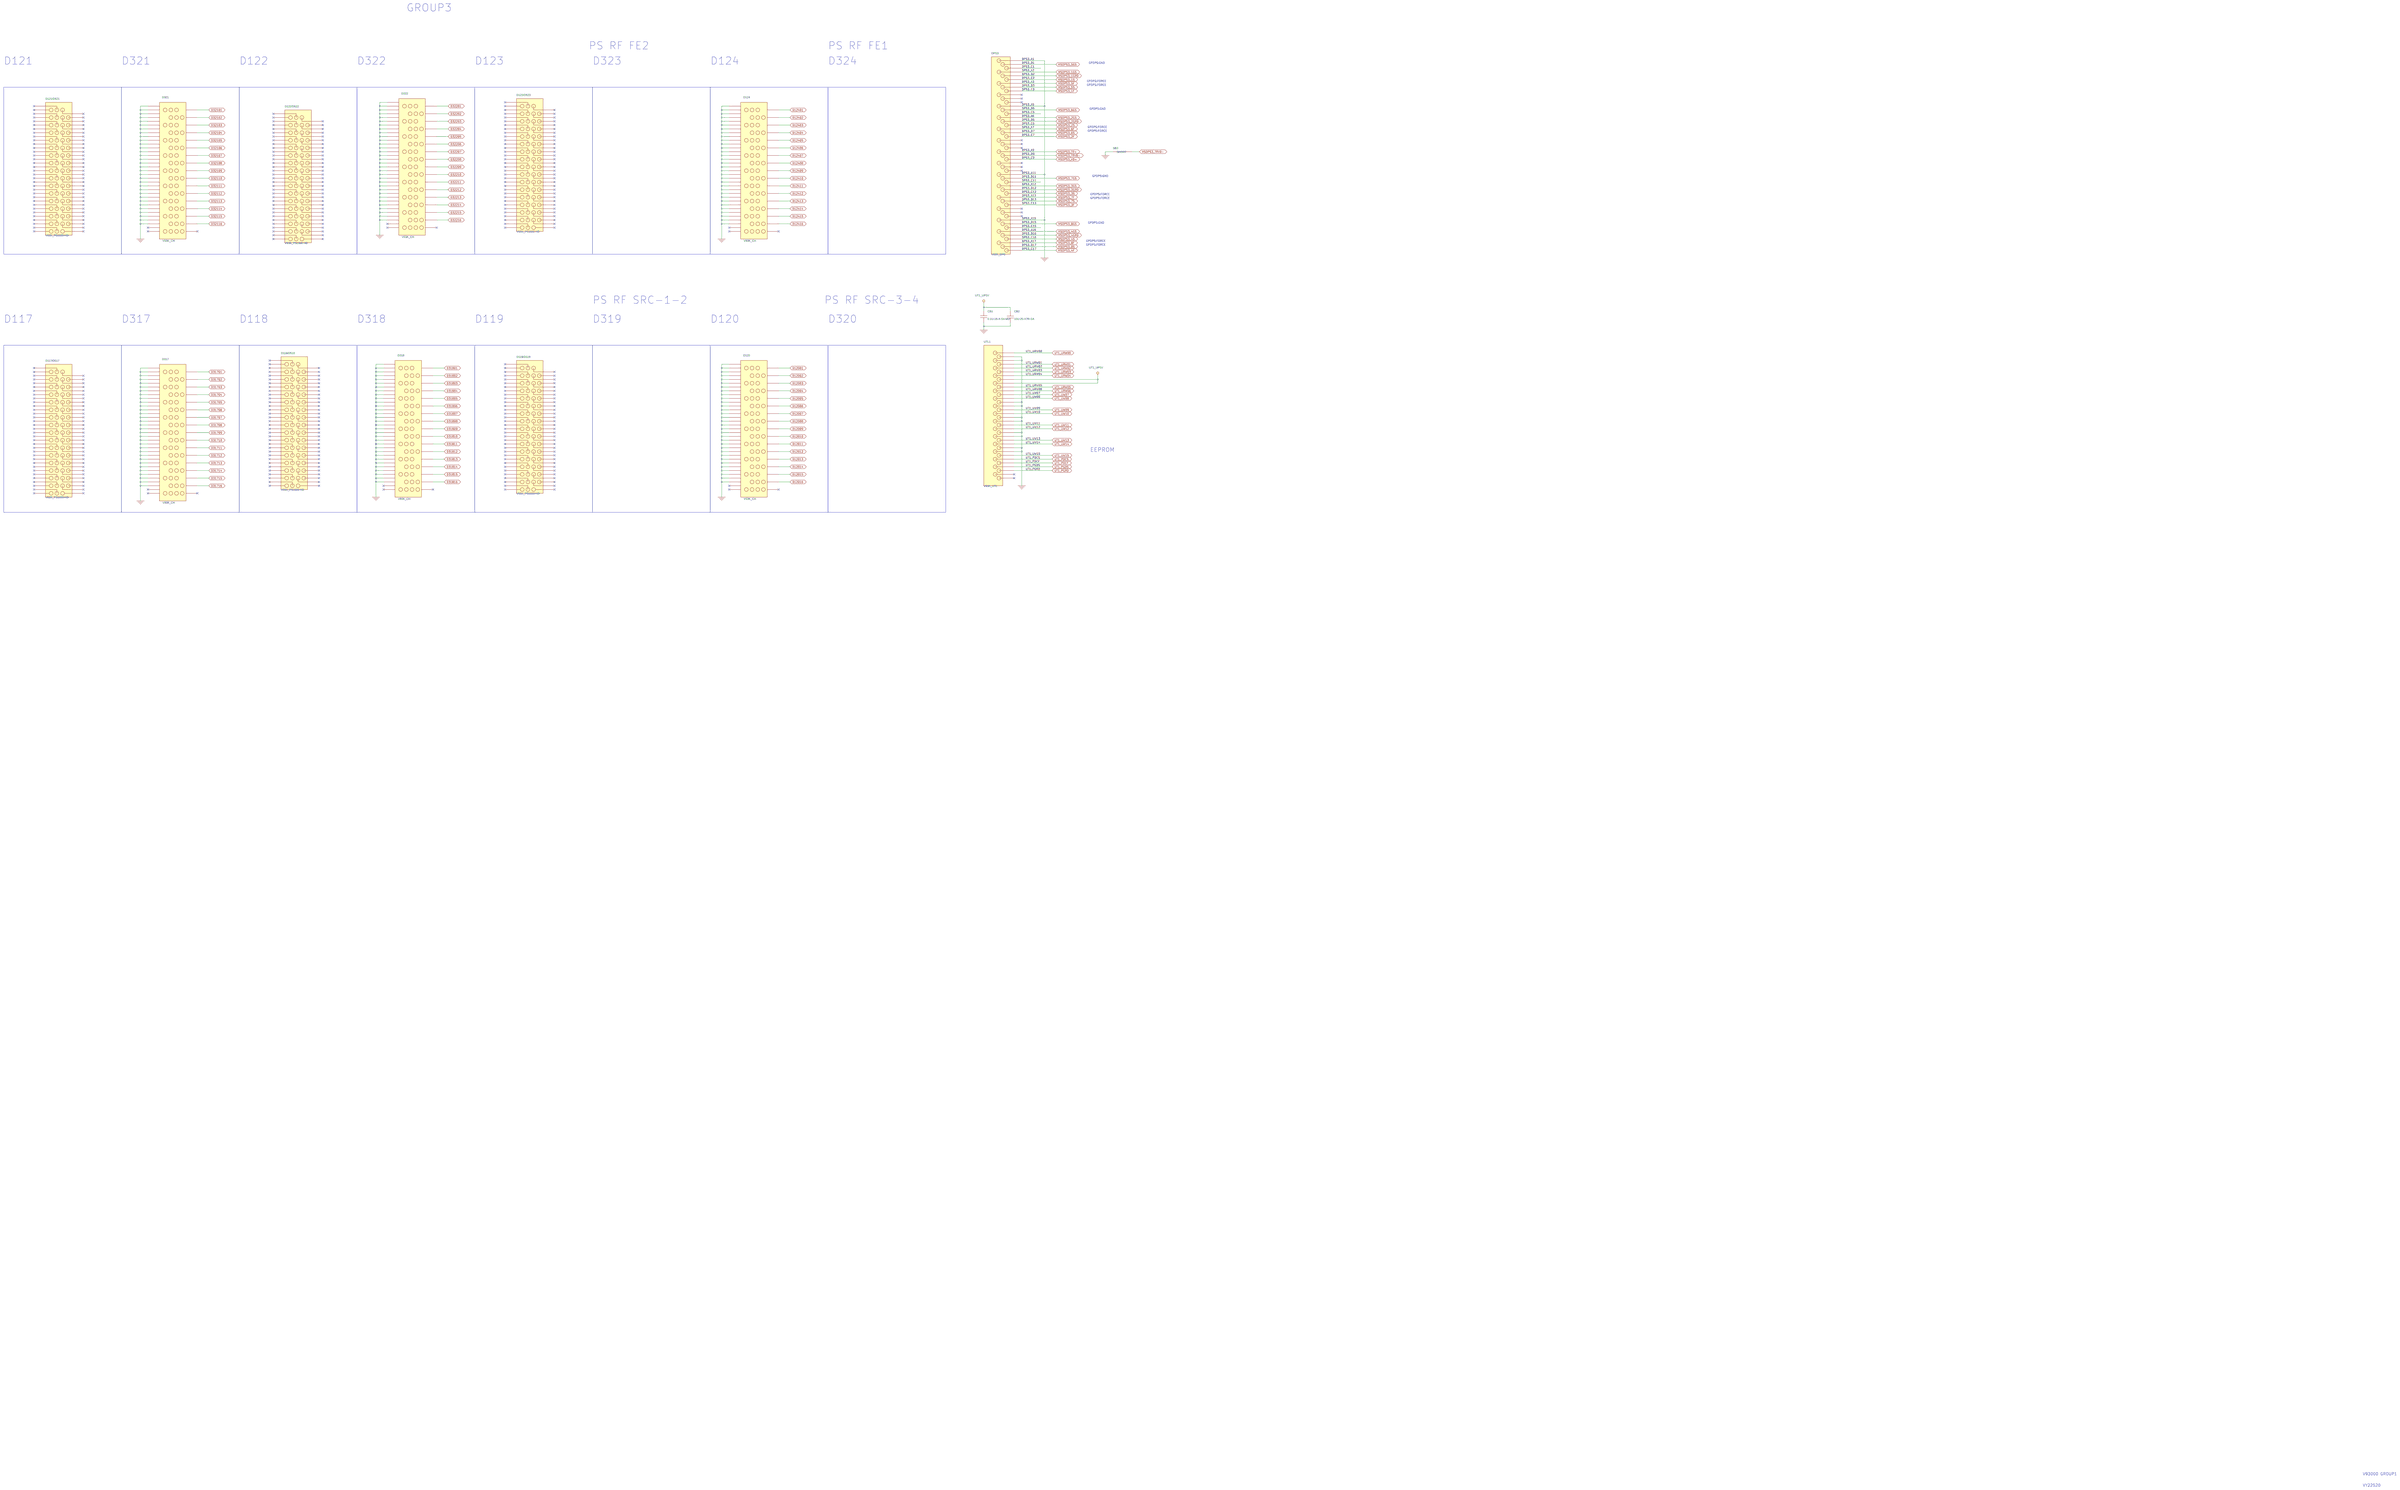
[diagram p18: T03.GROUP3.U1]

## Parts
sheet A0001-CONFIG
038HX-887904K4Q-A100  REF-CODE-PCB  [PCB_CODE]
980HX-887904-KAG-  REF-CODE-PCB  [PCB_CODE]
261103AA031  REF-CODE-SOCKET  [SOCKET_CODE]
HX8879-F04  REF-CODE-CHIP  [CHIP_CODE]
LOGO1  LOGO_KT_KSMT  [LOGO_KT_KSMT]
LOGO2  LOGO_HX_Himax  [LOGO_HX_Himax]
WFBGA-10X3.5X0.636-P0.65  REF-CODE-CHIP  [CHIP_CODE]
sheet P0011_S1_DUT
C53  0.1U-16-X-S4-MU  [C0402]
C54  0.1U-16-X-S4-MU  [C0402]
C55  0.1U-16-X-S4-MU  [C0402]
K9  UA2-5NJ-A-V3  [RL_NECUA2_5V_V3]
K10  UA2-5NJ-A-V3  [RL_NECUA2_5V_V3]
K48  UA2-5NJ-A-V3  [RL_NECUA2_5V_V3]
K50  UA2-5NJ-A-V3  [RL_NECUA2_5V_V3]
K54  G6K-2F-RF-T-5V-SPECIAL  [RL_G6K2FRT_8P_5V_GR]
K60  G6K-2F-RF-T-5V-SPECIAL  [RL_G6K2FRT_8P_5V_GR]
K61  G6K-2F-RF-T-5V-SPECIAL  [RL_G6K2FRT_8P_5V_GR]
K62  G6K-2F-RF-T-5V-SPECIAL  [RL_G6K2FRT_8P_5V_GR]
R11  49.9-1-S4  [R0402]
R12  49.9-1-S4  [R0402]
R13  49.9-1-S4  [R0402]
R14  49.9-1-S4  [R0402]
R15  49.9-1-S4  [R0402]
R16  49.9-1-S4  [R0402]
R17  49.9-1-S4  [R0402]
R18  49.9-1-S4  [R0402]
R19  49.9-1-S4  [R0402]
R20  49.9-1-S4  [R0402]
R21  49.9-1-S4  [R0402]
R22  49.9-1-S4  [R0402]
R23  49.9-1-S4  [R0402]
R24  49.9-1-S4  [R0402]
R25  49.9-1-S4  [R0402]
R26  49.9-1-S4  [R0402]
R51  NC/1M-1-S4  [R0402]
R52  NC/1M-1-S4  [R0402]
R53  NC/100K-1-S4  [R0402]
R54  NC/100K-1-S4  [R0402]
R55  100K-1-S4  [R0402]
R161  0-5-S4  [R0402]
R162  0-5-S4  [R0402]
R184  50-0.1-S4-HF-VI  [R0402]
R185  50-0.1-S4-HF-VI  [R0402]
SITE1  CU/887904-WFBGA75-10X3.5X0.636  [SK_WFBGA75P_0P65MM_JG_887904]  (sections A,B)
SW1  SW-SLIDE-1-D2.54-ECE  [SW_DIPX1_2P_H5MM]
sheet P0012_S1_FLASH_I2C
C1  0.1U-16-X-S4-MU  [C0402]
K14  UA2-5NJ-A-V3  [RL_NECUA2_5V_V3]
K15  UA2-5NJ-A-V3  [RL_NECUA2_5V_V3]
K28  UA2-5NJ-A-V3  [RL_NECUA2_5V_V3]
R69  NC/4.7K-1-S4  [R0402]
R70  NC/4.7K-1-S4  [R0402]
R71  NC/4.7K-1-S4  [R0402]
R72  4.7K-1-S4-WA  [R0402]
R73  NC/4.7K-1-S4  [R0402]
R74  NC/4.7K-1-S4  [R0402]
R147  1.1K-1-S4  [R0402]
R148  1.1K-1-S4  [R0402]
R163  4.7K-1-S4-WA  [R0402]
U5  SK-SO8-1.27-LOTES-150  [SK_SO8_150_1P27MM_LOTES]
UF1  MX25U4035FM1I-SOP8  [SOCKET_CODE]
sheet P0013_S1_POWER
C67  1U-10-X-S4-MU  [C0402]
C69  10U-25-X7R-SA  [C1206]
C70  10U-25-X7R-SA  [C1206]
C71  1U-10-X-S4-MU  [C0402]
C73  1U-10-X-S4-MU  [C0402]
C75  1U-10-X-S4-MU  [C0402]
C77  1U-10-X-S4-MU  [C0402]
C79  1U-10-X-S4-MU  [C0402]
C81  1U-10-X-S4-MU  [C0402]
C83  1U-10-X-S4-MU  [C0402]
C85  1U-10-X-S4-MU  [C0402]
C87  1U-10-X-S4-MU  [C0402]
C89  10U-25-X7R-SA  [C1206]
C90  10U-25-X7R-SA  [C1206]
C91  10U-25-X7R-SA  [C1206]
C92  10U-25-X7R-SA  [C1206]
C93  10U-25-X7R-SA  [C1206]
C94  10U-25-X7R-SA  [C1206]
C95  10U-25-X7R-SA  [C1206]
C96  10U-25-X7R-SA  [C1206]
CA1  NC/2.2U-10-X-S4-MU  [C0402]
CA2  NC/2.2U-10-X-S4-MU  [C0402]
CA3  NC/2.2U-10-X-S4-MU  [C0402]
CA4  NC/2.2U-10-X-S4-MU  [C0402]
CA5  NC/2.2U-10-X-S4-MU  [C0402]
CA6  NC/2.2U-10-X-S4-MU  [C0402]
CA7  NC/2.2U-10-X-S4-MU  [C0402]
CA8  NC/2.2U-10-X-S4-MU  [C0402]
CA9  NC/2.2U-10-X-S4-MU  [C0402]
CA10  NC/2.2U-10-X-S4-MU  [C0402]
CC1  0.47U-10-X6S-S2-TY  [C0201]
CC2  0.47U-10-X6S-S2-TY  [C0201]
CC3  0.47U-10-X6S-S2-TY  [C0201]
CC4  0.47U-10-X6S-S2-TY  [C0201]
CC5  0.47U-10-X6S-S2-TY  [C0201]
CC6  0.47U-10-X6S-S2-TY  [C0201]
CC7  0.47U-10-X6S-S2-TY  [C0201]
CC8  0.47U-10-X6S-S2-TY  [C0201]
CC9  0.47U-10-X6S-S2-TY  [C0201]
CC10  0.47U-10-X6S-S2-TY  [C0201]
CC11  0.47U-10-X6S-S2-TY  [C0201]
CC12  0.47U-10-X6S-S2-TY  [C0201]
CC13  0.47U-10-X6S-S2-TY  [C0201]
CC14  0.47U-10-X6S-S2-TY  [C0201]
CC15  0.47U-10-X6S-S2-TY  [C0201]
CD1  0.1U-10-X7R-S2-MU  [C0201]
CD2  0.1U-10-X7R-S2-MU  [C0201]
CD3  0.1U-10-X7R-S2-MU  [C0201]
CD4  0.1U-10-X7R-S2-MU  [C0201]
CD5  0.1U-10-X7R-S2-MU  [C0201]
CD6  0.1U-10-X7R-S2-MU  [C0201]
CD7  0.1U-10-X7R-S2-MU  [C0201]
CD8  0.1U-10-X7R-S2-MU  [C0201]
CD9  0.1U-10-X7R-S2-MU  [C0201]
CD10  0.1U-10-X7R-S2-MU  [C0201]
CD11  0.1U-10-X7R-S2-MU  [C0201]
CD12  0.1U-10-X7R-S2-MU  [C0201]
CD13  0.1U-10-X7R-S2-MU  [C0201]
CD14  0.1U-10-X7R-S2-MU  [C0201]
CD15  0.1U-10-X7R-S2-MU  [C0201]
GND1  TP01  [TP_040_T]
K55  EC2-5NJ-A  [RL_NECEC2_10P_5V]
K56  EC2-5NJ-A  [RL_NECEC2_10P_5V]
K57  EC2-5NJ-A  [RL_NECEC2_10P_5V]
K58  EC2-5NJ-A  [RL_NECEC2_10P_5V]
K59  EC2-5NJ-A  [RL_NECEC2_10P_5V]
R200  0-5-S4  [R0402]
R201  0-5-S4  [R0402]
R202  0-5-S4  [R0402]
R203  0-5-S4  [R0402]
R204  0-5-S4  [R0402]
R205  0-5-S4  [R0402]
R206  0-5-S4  [R0402]
R207  0-5-S4  [R0402]
R208  0-5-S4  [R0402]
R209  0-5-S4  [R0402]
SH1  SHORT  [DEFAULT_SHORT_SMALL]
SH2  SHORT  [DEFAULT_SHORT_SMALL]
SH3  SHORT  [DEFAULT_SHORT_SMALL]
SH4  SHORT  [DEFAULT_SHORT_SMALL]
SH5  SHORT  [DEFAULT_SHORT_SMALL]
SH6  SHORT  [DEFAULT_SHORT_SMALL]
SH7  SHORT  [DEFAULT_SHORT_SMALL]
SH8  SHORT  [DEFAULT_SHORT_SMALL]
SH9  SHORT  [DEFAULT_SHORT_SMALL]
SH10  SHORT  [DEFAULT_SHORT_SMALL]
SH11  SHORT  [DEFAULT_SHORT_SMALL]
SH12  SHORT  [DEFAULT_SHORT_SMALL]
SH13  SHORT  [DEFAULT_SHORT_SMALL]
SH14  SHORT  [DEFAULT_SHORT_SMALL]
SH15  SHORT  [DEFAULT_SHORT_SMALL]
SH16  SHORT  [DEFAULT_SHORT_SMALL]
SH17  SHORT  [DEFAULT_SHORT_SMALL]
SH18  SHORT  [DEFAULT_SHORT_SMALL]
SH19  SHORT  [DEFAULT_SHORT_SMALL]
SH20  SHORT  [DEFAULT_SHORT_SMALL]
TP_VDD09_CORE  TP01  [TP_040_T]
TP_VDD_IOB_18_BOOST  TP01  [TP_040_T]
TP_VDD_IOB_18_POR  TP01  [TP_040_T]
TP_VDD_PLL_09  TP01  [TP_040_T]
TP_VDD_TX_09  TP01  [TP_040_T]
TP_VDD_TX_09_HDO  TP01  [TP_040_T]
TP_VDD_TXPST_09  TP01  [TP_040_T]
TP_VDDIO_18  TP01  [TP_040_T]
TP_VDDRX_09  TP01  [TP_040_T]
TP_VDDRX_AUX  TP01  [TP_040_T]
sheet P0014-S1_PWR-OUT
CA12  NC/2.2U-10-X-S4-MU  [C0402]
CA13  NC/2.2U-10-X-S4-MU  [C0402]
CA14  NC/2.2U-10-X-S4-MU  [C0402]
SH21  SHORT  [DEFAULT_SHORT_SMALL]
SH22  SHORT  [DEFAULT_SHORT_SMALL]
SH23  SHORT  [DEFAULT_SHORT_SMALL]
SH24  SHORT  [DEFAULT_SHORT_SMALL]
SH25  SHORT  [DEFAULT_SHORT_SMALL]
SH26  SHORT  [DEFAULT_SHORT_SMALL]
TP_S1_V25  TP01  [TP_040_T]
TP_VDD_efuse_power  TP01  [TP_040_T]
TP_VDD_efuse_power1  TP01  [TP_040_T]
sheet S9999_MISC
BD29  BD120-3A-S8  [FB0805]
BD30  BD120-3A-S8  [FB0805]
BD31  BD120-3A-S8  [FB0805]
BD32  BD120-3A-S8  [FB0805]
BD33  BD120-3A-S8  [FB0805]
BD34  BD120-3A-S8  [FB0805]
BD35  BD120-3A-S8  [FB0805]
BD36  BD120-3A-S8  [FB0805]
BD37  BD120-3A-S8  [FB0805]
BD38  BD120-3A-S8  [FB0805]
BD39  BD120-3A-S8  [FB0805]
BD40  BD120-3A-S8  [FB0805]
BD41  BD120-3A-S8  [FB0805]
BD42  BD120-3A-S8  [FB0805]
BD43  BD120-3A-S8  [FB0805]
BD44  BD120-3A-S8  [FB0805]
CB19  0.1U-16-X-S4-MU  [C0402]
LDB1  LDB-2-S8  [LED_0805]
LRB1  330-1-S6  [R0603]
RB1  10K-1-S6  [R0603]
RB2  10K-1-S6  [R0603]
SB11  SHORT  [DEFAULT_SHORT_SMALL]
SB12  SHORT  [DEFAULT_SHORT_SMALL]
SCREW1  V93KMFHOLE  [PG_VG93K_F_FULLOUTLINE]
UB1  AT24C04C-SSHM-SO8  [SO8_215X127MM]
UT_UP5V  TP03-D  [TP_060_040]
sheet T01.GROUP1.U2
CB3  0.1U-16-X-S4-MU  [C0402]
CB4  10U-25-X7R-SA  [C1206]
D101/D501  V93K_PS1600 HD  [PG_VG93K_F_HSM_G1D101_501_ND]
D102/D502  V93K_PS1600 HD  [PG_VG93K_F_HSM_G1D102_502_ND]
D103/D503  V93K_PS1600 HD  [PG_VG93K_F_HSM_G1D103_503_ND]
D104  V93K_CH  [PG_VG93K_F_G1D104]
D105/D505  V93K_PS1600 HD  [PG_VG93K_F_HSM_G1D105_505_ND]
D106/D506  V93K_PS1600 HD  [PG_VG93K_F_HSM_G1D106_506_ND]
D107/D507  V93K_PS1600 HD  [PG_VG93K_F_HSM_G1D107_507_ND]
D108  V93K_CH  [PG_VG93K_F_G1D108]
D301  V93K_CH  [PG_VG93K_F_G1D301]
D302  V93K_CH  [PG_VG93K_F_G1D302]
D305  V93K_CH  [PG_VG93K_F_G1D305]
D306  V93K_CH  [PG_VG93K_F_G1D306]
DPS1  V93K_DPS  [PG_VG93K_F_G1DPS1]
SB1  SHORT  [DEFAULT_SHORT_SMALL]
UTL2  V93K_UTL  [PG_VG93K_F_G1UTI2]
sheet T02.GROUP2.U3
CB5  0.1U-16-X-S4-MU  [C0402]
CB6  10U-25-X7R-SA  [C1206]
D109  V93K_CH  [PG_VG93K_F_G2D109]
D110  V93K_CH  [PG_VG93K_F_G2D110]
D111  V93K_CH  [PG_VG93K_F_G2D111]
D112  V93K_CH  [PG_VG93K_F_G2D112]
D113  V93K_CH  [PG_VG93K_F_G2D113]
D114  V93K_CH  [PG_VG93K_F_G2D114]
D115  V93K_CH  [PG_VG93K_F_G2D115]
D116  V93K_CH  [PG_VG93K_F_G2D116]
DPS2  V93K_DPS  [PG_VG93K_F_G2DPS2]
SB2  SHORT  [DEFAULT_SHORT_SMALL]
UTL3  V93K_UTL  [PG_VG93K_F_G2UTI3]
sheet T03.GROUP3.U1
CB1  0.1U-16-X-S4-MU  [C0402]
CB2  10U-25-X7R-SA  [C1206]
D117/D517  V93K_PS1600 HD  [PG_VG93K_F_HSM_G3D117_517_ND]
D118/D518  V93K_PS1600 HD  [PG_VG93K_F_HSM_G3D118_518_ND]
D119/D519  V93K_PS1600 HD  [PG_VG93K_F_HSM_G3D119_519_ND]
D120  V93K_CH  [PG_VG93K_F_G3D120]
D121/D521  V93K_PS1600 HD  [PG_VG93K_F_HSM_G3D121_521_ND]
D122/D522  V93K_PS1600 HD  [PG_VG93K_F_HSM_G3D122_522_ND]
D123/D523  V93K_PS1600 HD  [PG_VG93K_F_HSM_G3D123_523_ND]
D124  V93K_CH  [PG_VG93K_F_G3D124]
D317  V93K_CH  [PG_VG93K_F_G3D317]
D318  V93K_CH  [PG_VG93K_F_G3D318]
D321  V93K_CH  [PG_VG93K_F_G3D321]
D322  V93K_CH  [PG_VG93K_F_G3D322]
DPS3  V93K_DPS  [PG_VG93K_F_G3DPS3]
SB3  SHORT  [DEFAULT_SHORT_SMALL]
UTL1  V93K_UTL  [PG_VG93K_F_G3UTI1]

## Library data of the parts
038HX-887904K4Q-A100 980HX-887904-KAG- = REF-CODE-PCB
261103AA031 = REF-CODE-SOCKET
HX8879-F04 WFBGA-10X3.5X0.636-P0.65 = REF-CODE-CHIP
LOGO1 = LOGO_KT_KSMT
LOGO2 = LOGO_HX_Himax
C1 C53-C55 CB1 CB3 CB5 CB19 = 0.1U-16-X-S4-MU
K9 K10 K14 K15 K28 K48 K50 = UA2-5NJ-A-V3
K54 K60-K62 = G6K-2F-RF-T-5V-SPECIAL
R11-R26 = 49.9-1-S4
R51 R52 = 1M-1-S4
R53-R55 = 100K-1-S4
R161 R162 R200-R209 = 0-5-S4
R184 R185 = 50-0.1-S4-HF-VI
SITE1 = CU_887904-WFBGA75-10X3.5X0.636
SW1 = SW-SLIDE-1-D2.54-ECE
R69-R74 R163 = 4.7K-1-S4-WA
R147 R148 = 1.1K-1-S4
U5 = MX25V4006EM1I-13G-SO8
UF1 = REF-CODE-FLASH
C67 C71 C73 C75 C77 C79 C81 C83 C85 C87 = 1U-10-X-S4-MU
C69 C70 C89-C96 CB2 CB4 CB6 = 10U-25-X7R-SA
CA1-CA10 CA12-CA14 = 2.2U-10-X-S4-MU
CC1-CC15 = 0.47U-10-X6S-S2-TY
CD1-CD15 = 0.1U-10-X7R-S2-MU
GND1 TP_S1_V25 TP_VDD09_CORE TP_VDD_efuse_power TP_VDD_efuse_power1 TP_VDD_IOB_18_BOOST TP_VDD_IOB_18_POR TP_VDD_PLL_09 TP_VDD_TX_09 TP_VDD_TX_09_HDO TP_VDD_TXPST_09 TP_VDDIO_18 TP_VDDRX_09 TP_VDDRX_AUX = TP01
K55-K59 = EC2-5NJ-A
SB1-SB3 SB11 SB12 SH1-SH26 = SHORT
BD29-BD44 = BD120-3A-S8
LDB1 = LDB-2-S8
LRB1 = 330-1-S6
RB1 RB2 = 10K-1-S6
SCREW1 = V93KMFHOLE
UB1 = AT24C04C-SSHM-SO8
UT_UP5V = TP03-D
D101/D501 D102/D502 D103/D503 D105/D505 D106/D506 D107/D507 D117/D517 D118/D518 D119/D519 D121/D521 D122/D522 D123/D523 = V93K_PS1600_HD
D104 D108-D116 D120 D124 D301 D302 D305 D306 D317 D318 D321 D322 = V93K_CH
DPS1-DPS3 = V93K_DPS
UTL1-UTL3 = V93K_UTL

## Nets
GND: BD29.1 BD30.1 BD31.1 BD32.1 BD33.1 BD34.1 BD35.1 BD36.1 BD37.1 BD38.1 BD39.1 BD40.1 BD41.1 BD42.1 BD43.1 BD44.1 C1.2 C55.1 C67.2 C69.2 C70.2 C71.2 C73.2 C75.2 C77.2 C79.2 C81.2 C83.2 C85.2 C87.2 C89.2 C90.2 C91.2 C92.2 C93.2 C94.2 C95.2 C96.2 CA1.2 CA2.2 CA3.2 CA4.2 CA5.2 CA6.2 CA7.2 CA8.2 CA9.2 CA10.2 CA12.2 CA13.2 CA14.2 CC1.2 CC2.2 CC3.2 CC4.2 CC5.2 CC6.2 CC7.2 CC8.2 CC9.2 CC10.2 CC11.2 CC12.2 CC13.2 CC14.2 CC15.2 CD1.2 CD2.2 CD3.2 CD4.2 CD5.2 CD6.2 CD7.2 CD8.2 CD9.2 CD10.2 CD11.2 CD12.2 CD13.2 CD14.2 CD15.2 D104.A1 D104.A2 D104.A3 D104.A4 D104.A5 D104.A6 D104.A7 D104.A8 D104.A9 D104.A10 D104.A11 D104.A12 D104.A13 D104.A14 D104.A15 D104.A16 D104.B1 D104.B2 D104.B3 D104.B4 D104.B5 D104.B6 D104.B7 D104.B8 D104.B9 D104.B10 D104.B11 D104.B12 D104.B13 D104.B14 D104.B15 D104.B16 D108.A1 D108.A2 D108.A3 D108.A4 D108.A5 D108.A6 D108.A7 D108.A8 D108.A9 D108.A10 D108.A11 D108.A12 D108.A13 D108.A14 D108.A15 D108.A16 D108.B1 D108.B2 D108.B3 D108.B4 D108.B5 D108.B6 D108.B7 D108.B8 D108.B9 D108.B10 D108.B11 D108.B12 D108.B13 D108.B14 D108.B15 D108.B16 D109.A1 D109.A2 D109.A3 D109.A4 D109.A5 D109.A6 D109.A7 D109.A8 D109.A9 D109.A10 D109.A11 D109.A12 D109.A13 D109.A14 D109.A15 D109.A16 D109.B1 D109.B2 D109.B3 D109.B4 D109.B5 D109.B6 D109.B7 D109.B8 D109.B9 D109.B10 D109.B11 D109.B12 D109.B13 D109.B14 D109.B15 D109.B16 D110.A1 D110.A2 D110.A3 D110.A4 D110.A5 D110.A6 D110.A7 D110.A8 D110.A9 D110.A10 D110.A11 D110.A12 D110.A13 D110.A14 D110.A15 D110.A16 D110.B1 D110.B2 D110.B3 D110.B4 D110.B5 D110.B6 D110.B7 D110.B8 D110.B9 D110.B10 D110.B11 D110.B12 D110.B13 D110.B14 D110.B15 D110.B16 D111.A1 D111.A2 D111.A3 D111.A4 D111.A5 D111.A6 D111.A7 D111.A8 D111.A9 D111.A10 D111.A11 D111.A12 D111.A13 D111.A14 D111.A15 D111.A16 D111.B1 D111.B2 D111.B3 D111.B4 D111.B5 D111.B6 D111.B7 D111.B8 D111.B9 D111.B10 D111.B11 D111.B12 D111.B13 D111.B14 D111.B15 D111.B16 D112.A1 D112.A2 D112.A3 D112.A4 D112.A5 D112.A6 D112.A7 D112.A8 D112.A9 D112.A10 D112.A11 D112.A12 D112.A13 D112.A14 D112.A15 D112.A16 D112.B1 D112.B2 D112.B3 D112.B4 D112.B5 D112.B6 D112.B7 D112.B8 D112.B9 D112.B10 D112.B11 D112.B12 D112.B13 D112.B14 D112.B15 D112.B16 D113.A1 D113.A2 D113.A3 D113.A4 D113.A5 D113.A6 D113.A7 D113.A8 D113.A9 D113.A10 D113.A11 D113.A12 D113.A13 D113.A14 D113.A15 D113.A16 D113.B1 D113.B2 D113.B3 D113.B4 D113.B5 D113.B6 D113.B7 D113.B8 D113.B9 D113.B10 D113.B11 D113.B12 D113.B13 D113.B14 D113.B15 D113.B16 D114.A1 D114.A2 D114.A3 D114.A4 D114.A5 D114.A6 D114.A7 D114.A8 D114.A9 D114.A10 D114.A11 D114.A12 D114.A13 D114.A14 D114.A15 D114.A16 D114.B1 D114.B2 D114.B3 D114.B4 D114.B5 D114.B6 D114.B7 D114.B8 D114.B9 D114.B10 D114.B11 D114.B12 D114.B13 D114.B14 D114.B15 D114.B16 D115.A1 D115.A2 D115.A3 D115.A4 D115.A5 D115.A6 D115.A7 D115.A8 D115.A9 D115.A10 D115.A11 D115.A12 D115.A13 D115.A14 D115.A15 D115.A16 D115.B1 D115.B2 D115.B3 D115.B4 D115.B5 D115.B6 D115.B7 D115.B8 D115.B9 D115.B10 D115.B11 D115.B12 D115.B13 D115.B14 D115.B15 D115.B16 D116.A1 D116.A2 D116.A3 D116.A4 D116.A5 D116.A6 D116.A7 D116.A8 D116.A9 D116.A10 D116.A11 D116.A12 D116.A13 D116.A14 D116.A15 D116.A16 D116.B1 D116.B2 D116.B3 D116.B4 D116.B5 D116.B6 D116.B7 D116.B8 D116.B9 D116.B10 D116.B11 D116.B12 D116.B13 D116.B14 D116.B15 D116.B16 D120.A1 D120.A2 D120.A3 D120.A4 D120.A5 D120.A6 D120.A7 D120.A8 D120.A9 D120.A10 D120.A11 D120.A12 D120.A13 D120.A14 D120.A15 D120.A16 D120.B1 D120.B2 D120.B3 D120.B4 D120.B5 D120.B6 D120.B7 D120.B8 D120.B9 D120.B10 D120.B11 D120.B12 D120.B13 D120.B14 D120.B15 D120.B16 D124.A1 D124.A2 D124.A3 D124.A4 D124.A5 D124.A6 D124.A7 D124.A8 D124.A9 D124.A10 D124.A11 D124.A12 D124.A13 D124.A14 D124.A15 D124.A16 D124.B1 D124.B2 D124.B3 D124.B4 D124.B5 D124.B6 D124.B7 D124.B8 D124.B9 D124.B10 D124.B11 D124.B12 D124.B13 D124.B14 D124.B15 D124.B16 D301.A1 D301.A2 D301.A3 D301.A4 D301.A5 D301.A6 D301.A7 D301.A8 D301.A9 D301.A10 D301.A11 D301.A12 D301.A13 D301.A14 D301.A15 D301.A16 D301.B1 D301.B2 D301.B3 D301.B4 D301.B5 D301.B6 D301.B7 D301.B8 D301.B9 D301.B10 D301.B11 D301.B12 D301.B13 D301.B14 D301.B15 D301.B16 D302.A1 D302.A2 D302.A3 D302.A4 D302.A5 D302.A6 D302.A7 D302.A8 D302.A9 D302.A10 D302.A11 D302.A12 D302.A13 D302.A14 D302.A15 D302.A16 D302.B1 D302.B2 D302.B3 D302.B4 D302.B5 D302.B6 D302.B7 D302.B8 D302.B9 D302.B10 D302.B11 D302.B12 D302.B13 D302.B14 D302.B15 D302.B16 D305.A1 D305.A2 D305.A3 D305.A4 D305.A5 D305.A6 D305.A7 D305.A8 D305.A9 D305.A10 D305.A11 D305.A12 D305.A13 D305.A14 D305.A15 D305.A16 D305.B1 D305.B2 D305.B3 D305.B4 D305.B5 D305.B6 D305.B7 D305.B8 D305.B9 D305.B10 D305.B11 D305.B12 D305.B13 D305.B14 D305.B15 D305.B16 D306.A1 D306.A2 D306.A3 D306.A4 D306.A5 D306.A6 D306.A7 D306.A8 D306.A9 D306.A10 D306.A11 D306.A12 D306.A13 D306.A14 D306.A15 D306.A16 D306.B1 D306.B2 D306.B3 D306.B4 D306.B5 D306.B6 D306.B7 D306.B8 D306.B9 D306.B10 D306.B11 D306.B12 D306.B13 D306.B14 D306.B15 D306.B16 D317.A1 D317.A2 D317.A3 D317.A4 D317.A5 D317.A6 D317.A7 D317.A8 D317.A9 D317.A10 D317.A11 D317.A12 D317.A13 D317.A14 D317.A15 D317.A16 D317.B1 D317.B2 D317.B3 D317.B4 D317.B5 D317.B6 D317.B7 D317.B8 D317.B9 D317.B10 D317.B11 D317.B12 D317.B13 D317.B14 D317.B15 D317.B16 D318.A1 D318.A2 D318.A3 D318.A4 D318.A5 D318.A6 D318.A7 D318.A8 D318.A9 D318.A10 D318.A11 D318.A12 D318.A13 D318.A14 D318.A15 D318.A16 D318.B1 D318.B2 D318.B3 D318.B4 D318.B5 D318.B6 D318.B7 D318.B8 D318.B9 D318.B10 D318.B11 D318.B12 D318.B13 D318.B14 D318.B15 D318.B16 D321.A1 D321.A2 D321.A3 D321.A4 D321.A5 D321.A6 D321.A7 D321.A8 D321.A9 D321.A10 D321.A11 D321.A12 D321.A13 D321.A14 D321.A15 D321.A16 D321.B1 D321.B2 D321.B3 D321.B4 D321.B5 D321.B6 D321.B7 D321.B8 D321.B9 D321.B10 D321.B11 D321.B12 D321.B13 D321.B14 D321.B15 D321.B16 D322.A1 D322.A2 D322.A3 D322.A4 D322.A5 D322.A6 D322.A7 D322.A8 D322.A9 D322.A10 D322.A11 D322.A12 D322.A13 D322.A14 D322.A15 D322.A16 D322.B1 D322.B2 D322.B3 D322.B4 D322.B5 D322.B6 D322.B7 D322.B8 D322.B9 D322.B10 D322.B11 D322.B12 D322.B13 D322.B14 D322.B15 D322.B16 DPS1.A01 DPS1.A05 DPS1.A11 DPS1.A15 DPS2.A01 DPS2.A05 DPS2.A11 DPS2.A15 DPS3.A01 DPS3.A05 DPS3.A11 DPS3.A15 GND1.1(TP) K54.G1 K54.G2 K54.G3 K54.G4 K54.G5 K54.G6 K54.G7 K54.G8 K54.G9 K54.G10 K60.G1 K60.G2 K60.G3 K60.G4 K60.G5 K60.G6 K60.G7 K60.G8 K60.G9 K60.G10 K61.G1 K61.G2 K61.G3 K61.G4 K61.G5 K61.G6 K61.G7 K61.G8 K61.G9 K61.G10 K62.G1 K62.G2 K62.G3 K62.G4 K62.G5 K62.G6 K62.G7 K62.G8 K62.G9 K62.G10 R51.1 R54.1 R163.1 R184.2 R185.2 SB1.1 SB2.1 SB3.1 SH2.2 SH4.2 SH5.2 SH8.2 SH9.2 SH11.2 SH13.2 SH15.2 SH17.2 SH19.2 SH21.2 SH23.2 SH25.2 SITE1.B4(VSS_CORE_09[1]) SITE1.B5(VSS_CORE_09[2]) SITE1.C12(VSS_CORE_09[3]) SITE1.C13(VSS_CORE_09[4]) U5.4(GND) ; also on sheet 1 2 3 4 5 6 7 8 9 20 21 22 23 24
D10401: D104.01
D10402: D104.02
D10403: D104.03
D10404: D104.04
D10405: D104.05
D10406: D104.06
D10407: D104.07
D10408: D104.08
D10409: D104.09
D10410: D104.10
D10411: D104.11
D10412: D104.12
D10413: D104.13
D10414: D104.14
D10415: D104.15
D10416: D104.16
D10801: D108.01
D10802: D108.02
D10803: D108.03
D10804: D108.04
D10805: D108.05
D10806: D108.06
D10807: D108.07
D10808: D108.08
D10809: D108.09
D10810: D108.10
D10811: D108.11
D10812: D108.12
D10813: D108.13
D10814: D108.14
D10815: D108.15
D10816: D108.16
D10901: D109.01
D10902: D109.02
D10903: D109.03
D10904: D109.04
D10905: D109.05
D10906: D109.06
D10907: D109.07
D10908: D109.08
D10909: D109.09
D10910: D109.10
D10911: D109.11
D10912: D109.12
D10913: D109.13
D10914: D109.14
D10915: D109.15
D10916: D109.16
D11001: D110.01
D11002: D110.02
D11003: D110.03
D11004: D110.04
D11005: D110.05
D11006: D110.06
D11007: D110.07
D11008: D110.08
D11009: D110.09
D11010: D110.10
D11011: D110.11
D11012: D110.12
D11013: D110.13
D11014: D110.14
D11015: D110.15
D11016: D110.16
D11101: D111.01
D11102: D111.02
D11103: D111.03
D11104: D111.04
D11105: D111.05
D11106: D111.06
D11107: D111.07
D11108: D111.08
D11109: D111.09
D11110: D111.10
D11111: D111.11
D11112: D111.12
D11113: D111.13
D11114: D111.14
D11115: D111.15
D11116: D111.16
D11201: D112.01
D11202: D112.02
D11203: D112.03
D11204: D112.04
D11205: D112.05
D11206: D112.06
D11207: D112.07
D11208: D112.08
D11209: D112.09
D11210: D112.10
D11211: D112.11
D11212: D112.12
D11213: D112.13
D11214: D112.14
D11215: D112.15
D11216: D112.16
D11301: D113.01
D11302: D113.02
D11303: D113.03
D11304: D113.04
D11305: D113.05
D11306: D113.06
D11307: D113.07
D11308: D113.08
D11309: D113.09
D11310: D113.10
D11311: D113.11
D11312: D113.12
D11313: D113.13
D11314: D113.14
D11315: D113.15
D11316: D113.16
D11401: D114.01
D11402: D114.02
D11403: D114.03
D11404: D114.04
D11405: D114.05
D11406: D114.06
D11407: D114.07
D11408: D114.08
D11409: D114.09
D11410: D114.10
D11411: D114.11
D11412: D114.12
D11413: D114.13
D11414: D114.14
D11415: D114.15
D11416: D114.16
D11501: D115.01
D11502: D115.02
D11503: D115.03
D11504: D115.04
D11505: D115.05
D11506: D115.06
D11507: D115.07
D11508: D115.08
D11509: D115.09
D11510: D115.10
D11511: D115.11
D11512: D115.12
D11513: D115.13
D11514: D115.14
D11515: D115.15
D11516: D115.16
D11601: D116.01
D11602: D116.02
D11603: D116.03
D11604: D116.04
D11605: D116.05
D11606: D116.06
D11607: D116.07
D11608: D116.08
D11609: D116.09
D11610: D116.10
D11611: D116.11
D11612: D116.12
D11613: D116.13
D11614: D116.14
D11615: D116.15
D11616: D116.16 ; also on sheet 20
D12001: D120.01
D12002: D120.02
D12003: D120.03
D12004: D120.04
D12005: D120.05
D12006: D120.06
D12007: D120.07
D12008: D120.08
D12009: D120.09
D12010: D120.10
D12011: D120.11
D12012: D120.12
D12013: D120.13
D12014: D120.14
D12015: D120.15
D12016: D120.16
D12401: D124.01
D12402: D124.02
D12403: D124.03
D12404: D124.04
D12405: D124.05
D12406: D124.06
D12407: D124.07
D12408: D124.08
D12409: D124.09
D12410: D124.10 SB12.2
D12411: D124.11 SB11.2
D12412: D124.12
D12413: D124.13
D12414: D124.14
D12415: D124.15
D12416: D124.16
D30101: D301.01
D30102: D301.02
D30103: D301.03
D30104: D301.04
D30105: D301.05
D30106: D301.06
D30107: D301.07
D30108: D301.08
D30109: D301.09
D30110: D301.10
D30111: D301.11
D30112: D301.12
D30113: D301.13
D30114: D301.14
D30115: D301.15
D30116: D301.16
D30201: D302.01
D30202: D302.02
D30203: D302.03
D30204: D302.04
D30205: D302.05
D30206: D302.06
D30207: D302.07
D30208: D302.08
D30209: D302.09
D30210: D302.10
D30211: D302.11
D30212: D302.12
D30213: D302.13
D30214: D302.14
D30215: D302.15
D30216: D302.16
D30501: D305.01
D30502: D305.02
D30503: D305.03
D30504: D305.04
D30505: D305.05
D30506: D305.06
D30507: D305.07
D30508: D305.08
D30509: D305.09
D30510: D305.10
D30511: D305.11
D30512: D305.12
D30513: D305.13
D30514: D305.14
D30515: D305.15
D30516: D305.16
D30601: D306.01
D30602: D306.02
D30603: D306.03
D30604: D306.04
D30605: D306.05
D30606: D306.06
D30607: D306.07
D30608: D306.08
D30609: D306.09
D30610: D306.10
D30611: D306.11
D30612: D306.12
D30613: D306.13
D30614: D306.14
D30615: D306.15
D30616: D306.16
D31701: D317.01
D31702: D317.02
D31703: D317.03
D31704: D317.04
D31705: D317.05
D31706: D317.06
D31707: D317.07
D31708: D317.08
D31709: D317.09
D31710: D317.10
D31711: D317.11
D31712: D317.12
D31713: D317.13
D31714: D317.14
D31715: D317.15
D31716: D317.16
D31801: D318.01
D31802: D318.02
D31803: D318.03
D31804: D318.04
D31805: D318.05
D31806: D318.06
D31807: D318.07
D31808: D318.08
D31809: D318.09
D31810: D318.10
D31811: D318.11
D31812: D318.12
D31813: D318.13
D31814: D318.14
D31815: D318.15
D31816: D318.16
D32101: D321.01
D32102: D321.02
D32103: D321.03
D32104: D321.04
D32105: D321.05
D32106: D321.06
D32107: D321.07
D32108: D321.08
D32109: D321.09
D32110: D321.10
D32111: D321.11
D32112: D321.12
D32113: D321.13
D32114: D321.14
D32115: D321.15
D32116: D321.16
D32201: D322.01
D32202: D322.02
D32203: D322.03
D32204: D322.04
D32205: D322.05
D32206: D322.06
D32207: D322.07
D32208: D322.08
D32209: D322.09
D32210: D322.10
D32211: D322.11
D32212: D322.12
D32213: D322.13
D32214: D322.14
D32215: D322.15
D32216: D322.16
DPS1_C1: DPS1.C01
DPS1_C5: DPS1.C05
DPS1_C11: DPS1.C11
DPS1_C15: DPS1.C15
DPS2_C1: DPS2.C01
DPS2_C5: DPS2.C05
DPS2_C11: DPS2.C11
DPS2_C15: DPS2.C15
DPS3_C1: DPS3.C01
DPS3_C5: DPS3.C05
DPS3_C11: DPS3.C11
DPS3_C15: DPS3.C15
MSDPS1_1F: DPS1.C03
MSDPS1_1GRD: DPS1.B02
MSDPS1_1GS: DPS1.A02
MSDPS1_1S: DPS1.C02
MSDPS1_2F: DPS1.C07
MSDPS1_2GRD: DPS1.B06
MSDPS1_2GS: DPS1.A06
MSDPS1_2S: DPS1.C06
MSDPS1_3F: DPS1.C13
MSDPS1_3GRD: DPS1.B12
MSDPS1_3GS: DPS1.A12
MSDPS1_3S: DPS1.C12
MSDPS1_4F: DPS1.C17
MSDPS1_4GRD: DPS1.B16
MSDPS1_4GS: DPS1.A16
MSDPS1_4S: DPS1.C16
MSDPS1_5F: DPS1.A03
MSDPS1_5GS: DPS1.B01
MSDPS1_5S: DPS1.B03
MSDPS1_6F: DPS1.A07
MSDPS1_6GS: DPS1.B05
MSDPS1_6S: DPS1.B07
MSDPS1_7F: DPS1.A13
MSDPS1_7GS: DPS1.B11
MSDPS1_7S: DPS1.B13
MSDPS1_8F: DPS1.A17
MSDPS1_8GS: DPS1.B15
MSDPS1_8S: DPS1.B17
MSDPS1_TR+: DPS1.A09 DPS2.A09 DPS3.A09 SB11.1 ; also on sheet 20
MSDPS1_TRVB-: DPS1.B09 SB1.2
MSDPS1_VB+: DPS1.C09 DPS2.C09 DPS3.C09 SB12.1 ; also on sheet 20
MSDPS2_1F: DPS2.C03
MSDPS2_1GRD: DPS2.B02
MSDPS2_1GS: DPS2.A02
MSDPS2_1S: DPS2.C02
MSDPS2_2F: DPS2.C07
MSDPS2_2GRD: DPS2.B06
MSDPS2_2GS: DPS2.A06
MSDPS2_2S: DPS2.C06
MSDPS2_3F: DPS2.C13
MSDPS2_3GRD: DPS2.B12
MSDPS2_3GS: DPS2.A12
MSDPS2_3S: DPS2.C12
MSDPS2_4F: DPS2.C17
MSDPS2_4GRD: DPS2.B16
MSDPS2_4GS: DPS2.A16
MSDPS2_4S: DPS2.C16
MSDPS2_5F: DPS2.A03
MSDPS2_5GS: DPS2.B01
MSDPS2_5S: DPS2.B03
MSDPS2_6F: DPS2.A07
MSDPS2_6GS: DPS2.B05
MSDPS2_6S: DPS2.B07
MSDPS2_7F: DPS2.A13
MSDPS2_7GS: DPS2.B11
MSDPS2_7S: DPS2.B13
MSDPS2_8F: DPS2.A17
MSDPS2_8GS: DPS2.B15
MSDPS2_8S: DPS2.B17
MSDPS2_TRVB-: DPS2.B09 SB2.2
MSDPS3_1F: DPS3.C03
MSDPS3_1GRD: DPS3.B02
MSDPS3_1GS: DPS3.A02
MSDPS3_1S: DPS3.C02
MSDPS3_2F: DPS3.C07
MSDPS3_2GRD: DPS3.B06
MSDPS3_2GS: DPS3.A06
MSDPS3_2S: DPS3.C06
MSDPS3_3F: DPS3.C13
MSDPS3_3GRD: DPS3.B12
MSDPS3_3GS: DPS3.A12
MSDPS3_3S: DPS3.C12
MSDPS3_4F: DPS3.C17
MSDPS3_4GRD: DPS3.B16
MSDPS3_4GS: DPS3.A16
MSDPS3_4S: DPS3.C16
MSDPS3_5F: DPS3.A03
MSDPS3_5GS: DPS3.B01
MSDPS3_5S: DPS3.B03
MSDPS3_6F: DPS3.A07
MSDPS3_6GS: DPS3.B05
MSDPS3_6S: DPS3.B07
MSDPS3_7F: DPS3.A13
MSDPS3_7GS: DPS3.B11
MSDPS3_7S: DPS3.B13
MSDPS3_8F: DPS3.A17
MSDPS3_8GS: DPS3.B15
MSDPS3_8S: DPS3.B17
MSDPS3_TRVB-: DPS3.B09 SB3.2
S1_AUX1+: K9.5 R162.1
S1_AUX1-: K9.4 R161.1
S1_AUX2+: C54.2 R52.1 R54.2 R162.2
S1_AUX2-: C53.2 R51.2 R53.2 R161.2
S1_AUX+: K9.6 K50.6 SITE1.D14(AUX_P)
S1_AUX-: K9.3 K50.3 SITE1.E14(AUX_N)
S1_AUX_100DCH001+: K9.7
S1_AUX_100DCH001-: K9.2
S1_AUX_100DCH003+: C54.1
S1_AUX_100DCH003-: C53.1
S1_DCH005: SITE1.A14(HPD)
S1_DCH006: K10.3 SITE1.A1(RESET)
S1_DCH007: SITE1.B15(BIST)
S1_DCH009: SITE1.C15(CABC_EN)
S1_DCH010: SITE1.A15(PWMI)
S1_DCH011: SITE1.E3(PWMO)
S1_DCH012: K28.6 SITE1.C1(I2C_SDA)
S1_DCH013: K28.3 SITE1.D1(I2C_SCL)
S1_DCH014: K48.2
S1_DCH015: SITE1.E5(GPIO1)
S1_DCH016: SITE1.D5(GPIO2)
S1_DCH017: SITE1.D6(GPIO3)
S1_DCH018: SITE1.D7(GPIO4)
S1_DCH019: SITE1.D8(GPIO5)
S1_DCH020: SITE1.E6(GPIO6)
S1_DCH021: SITE1.D3(GPIO7)
S1_DCH022: SITE1.E4(GPIO8)
S1_DCH023: SITE1.C2(GPIO9)
S1_DCH024: SITE1.D15(GPIO10)
S1_DCH025: SITE1.B1(STV1)
S1_DCH026: SITE1.D2(STV2)
S1_DCH027: SITE1.B2(CPV)
S1_DCH028: SITE1.E1(OE1)
S1_DCH029: SITE1.E2(OE2)
S1_DCH030: SITE1.A3(XSTB)
S1_DCH031: SITE1.A2(SD_LOCK)
S1_DCH032: R200.2
S1_DCH033: R201.2
S1_DCH034: R202.2
S1_DCH035: R203.2
S1_DCH036: R204.2
S1_DCH037: R205.2
S1_DCH038: R206.2
S1_DCH039: R207.2
S1_DCH040: R208.2
S1_DCH041: R209.2
S1_DCH42: K15.2
S1_DCH43: K15.7
S1_DCH44: K14.2
S1_DCH45: K14.7
S1_DPS_F01: C67.1 CA1.1 CC1.1 CC2.1 CC3.1 CC4.1 CD1.1 CD2.1 CD3.1 CD4.1 K55.4 R200.1 SH1.2 SITE1.C4(VDD_CORE_09[1]) SITE1.C8(VDD_CORE_09[2]) SITE1.C9(VDD_CORE_09[3]) SITE1.C10(VDD_CORE_09[4]) TP_VDD09_CORE.1(TP)
S1_DPS_F03: C71.1 CA2.1 CC5.1 CC6.1 CC7.1 CD5.1 CD6.1 CD7.1 K56.4 R55.2 R201.1 SH3.2 SITE1.C5(VDD_IO_18[2]) SITE1.C6(VDD_IO_18[3]) SITE1.C11(VDD_IO_18[1]) TP_VDDIO_18.1(TP)
S1_DPS_F04: C73.1 CA3.1 CC8.1 CD8.1 K57.9 R202.1 SH6.2 SITE1.A5(VDD_TX_09_HDO) TP_VDD_TX_09_HDO.1(TP)
S1_DPS_F05: C75.1 CA4.1 CC9.1 CD9.1 K58.4 R203.1 SH7.2 SITE1.C7(VDD_TXPST_09) TP_VDD_TXPST_09.1(TP)
S1_DPS_F06: C77.1 CA5.1 CC10.1 CD10.1 K58.9 R204.1 SH10.2 SITE1.A4(VDD_TX_09) TP_VDD_TX_09.1(TP)
S1_DPS_F07: C79.1 CA6.1 CC11.1 CD11.1 K59.4 R205.1 SH12.2 SITE1.C14(VDDRX_AUX_09) TP_VDDRX_AUX.1(TP)
S1_DPS_F08: C81.1 CA7.1 CC12.1 CD12.1 K56.9 R206.1 SH14.2 SITE1.E15(VDDRX_09) TP_VDDRX_09.1(TP)
S1_DPS_F09: C83.1 CA8.1 CC13.1 CD13.1 K59.9 R207.1 SH16.2 SITE1.B3(VDD_PLL_09) TP_VDD_PLL_09.1(TP)
S1_DPS_F10: C85.1 CA9.1 CC14.1 CD14.1 K55.9 R208.1 SH18.2 SITE1.B14(VDD_IOB_18_BOOST) TP_VDD_IOB_18_BOOST.1(TP)
S1_DPS_F11: C87.1 CA10.1 CC15.1 CD15.1 K57.4 R209.1 SH20.2 SITE1.C3(VDD_IOB_18_POR) TP_VDD_IOB_18_POR.1(TP)
S1_DPS_F12: CA12.1 R52.2 R53.1 SH22.2 TP_S1_V25.1(TP)
S1_DPS_F13: CA13.1 K48.4 SH24.2 TP_VDD_efuse_power.1(TP)
S1_DPS_F14: C1.1 CA14.1 R69.1 R70.1 R71.1 R72.1 R73.1 R74.1 R147.2 R148.2 SH26.2 TP_VDD_efuse_power1.1(TP) U5.8(VCC)
S1_DPS_FS01: SH1.1
S1_DPS_FS03: SH3.1
S1_DPS_FS04: SH6.1
S1_DPS_FS05: SH7.1
S1_DPS_FS06: SH10.1
S1_DPS_FS07: SH12.1
S1_DPS_FS08: SH14.1
S1_DPS_FS09: SH16.1
S1_DPS_FS10: SH18.1
S1_DPS_FS11: SH20.1
S1_DPS_FS12: SH22.1
S1_DPS_FS13: SH24.1
S1_DPS_FS14: SH26.1
S1_DPS_GS01: SH2.1
S1_DPS_GS03: SH4.1
S1_DPS_GS04: SH5.1
S1_DPS_GS05: SH8.1
S1_DPS_GS06: SH9.1
S1_DPS_GS07: SH11.1
S1_DPS_GS08: SH13.1
S1_DPS_GS09: SH15.1
S1_DPS_GS10: SH17.1
S1_DPS_GS11: SH19.1
S1_DPS_GS12: SH21.1
S1_DPS_GS13: SH23.1
S1_DPS_GS14: SH25.1
S1_RLY01: K9.8(V-)
S1_RLY02: K50.8(V-)
S1_RLY03: K10.8(V-)
S1_RLY04: K48.8(V-)
S1_RLY08: K54.8(V-)
S1_RLY09: K61.8(V-)
S1_RLY20: K55.12(V-)
S1_RLY22: K57.12(V-)
S1_RLY24: K59.12(V-)
S1_RLY27: K15.8(V-)
S1_RLY43: K60.8(V-)
S1_RLY44: K62.8(V-)
S1_RLY45: K14.8(V-)
S1_RLY46: K28.8(V-)
S1_RLY47: K56.12(V-)
S1_RLY48: K58.12(V-)
S1_ROM_SPI_CS: K15.6 SITE1.E7(ROM_SPI_CS)
S1_ROM_SPI_SCK: K15.3 SITE1.E8(ROM_SPI_SCK)
S1_ROM_SPI_SDI: K14.6 SITE1.E9(ROM_SPI_SDI)
S1_ROM_SPI_SDO: K14.3 SITE1.D9(ROM_SPI_SDO)
S1_RX_85DCH00+: SITE1.E10(RX_N0)
S1_RX_85DCH00-: SITE1.D10(RX_P0)
S1_RX_85DCH01+: SITE1.E11(RX_N1)
S1_RX_85DCH01-: SITE1.D11(RX_P1)
S1_RX_85DCH02+: SITE1.D12(RX_N2)
S1_RX_85DCH02-: SITE1.E12(RX_P2)
S1_RX_85DCH03+: SITE1.D13(RX_N3)
S1_RX_85DCH03-: SITE1.E13(RX_P3)
S1_SPI_1_CSN: K15.5 R69.2 U5.1(CS#)
S1_SPI_1_SCK: K15.4 R73.2 U5.6(SCLK)
S1_SPI_1_SDI: K14.5 R70.2 U5.2(SO)
S1_SPI_1_SDO: K14.4 R74.2 U5.5(SI)
S1_TEST: K48.3 SITE1.D4(TEST)
S1_TX_100DCH0_N: R11.1 SITE1.A13(TX0_N)
S1_TX_100DCH0_P: R12.2 SITE1.B13(TX0_P)
S1_TX_100DCH1_N: R13.1 SITE1.B12(TX1_N)
S1_TX_100DCH1_P: R14.2 SITE1.A12(TX1_P)
S1_TX_100DCH2_N: R15.1 SITE1.B11(TX2_N)
S1_TX_100DCH2_P: R16.2 SITE1.A11(TX2_P)
S1_TX_100DCH3_N: R17.1 SITE1.B10(TX3_N)
S1_TX_100DCH3_P: R18.2 SITE1.A10(TX3_P)
S1_TX_100DCH4_N: R19.1 SITE1.A9(TX4_N)
S1_TX_100DCH4_P: R20.2 SITE1.B9(TX4_P)
S1_TX_100DCH5_N: R21.1 SITE1.A8(TX5_N)
S1_TX_100DCH5_P: R22.2 SITE1.B8(TX5_P)
S1_TX_100DCH6_N: R23.1 SITE1.A7(TX6_N)
S1_TX_100DCH6_P: R24.2 SITE1.B7(TX6_P)
S1_TX_100DCH7_N: R25.1 SITE1.B6(TX7_N)
S1_TX_100DCH7_P: R26.2 SITE1.A6(TX7_P)
UDBGND: BD29.2 BD30.2 BD31.2 BD32.2 BD33.2 BD34.2 BD35.2 BD36.2 BD37.2 BD38.2 BD39.2 BD40.2 BD41.2 BD42.2 BD43.2 BD44.2 CB1.2 CB2.1 CB3.2 CB4.1 CB5.2 CB6.1 CB19.2 LDB1.2(B) UB1.1(NC) UB1.2(A1/NC) UB1.3(A2) UB1.4(GND) UB1.7(WP) UTL1.A02 UTL1.A08 UTL1.A10 UTL1.A12 UTL1.A14 UTL1.B01 UTL1.B07 UTL1.B09 UTL1.B11 UTL1.B13 UTL2.A02 UTL2.A08 UTL2.A10 UTL2.A12 UTL2.A14 UTL2.B01 UTL2.B07 UTL2.B09 UTL2.B11 UTL2.B13 UTL3.A02 UTL3.A08 UTL3.A10 UTL3.A12 UTL3.A14 UTL3.B01 UTL3.B07 UTL3.B09 UTL3.B11 UTL3.B13 ; also on sheet 20 21 22 23 24
UT1_PDCF: UTL1.B15
UT1_PDCS: UTL1.A15
UT1_PGDS: UTL1.A16
UT1_PGRD: UTL1.B16
UT1_UP5V: CB1.1 CB2.2 CB3.1 CB4.2 CB5.1 CB6.2 CB19.1 K9.1(V+) K10.1(V+) K14.1(V+) K15.1(V+) K28.1(V+) K48.1(V+) K50.1(V+) K54.1(V+) K55.1(V+) K56.1(V+) K57.1(V+) K58.1(V+) K59.1(V+) K60.1(V+) K61.1(V+) K62.1(V+) LRB1.1 RB1.1 RB2.1 UB1.8(VCC) UT_UP5V.1(TP) UTL1.A05 UTL1.B04 UTL2.A05 UTL2.B04 UTL3.A05 UTL3.B04 ; also on sheet 1 2 3 4 5 6 7 8 9 20 21 22 23 24
UT1_URW00: UTL1.A01
UT1_URW01: UTL1.B02
UT1_URW02: UTL1.A03
UT1_URW03: UTL1.B03
UT1_URW04: UTL1.A04
UT1_URW05: UTL1.B05
UT1_URW06: UTL1.A06
UT1_UW07: UTL1.B06
UT1_UW08: UTL1.A07
UT1_UW09: UTL1.B08
UT1_UW10: UTL1.A09
UT1_UW11: UTL1.B10
UT1_UW12: UTL1.A11
UT1_UW13: UTL1.B12
UT1_UW14: RB1.2 UB1.6(SCL) UTL1.A13
UT1_UW15: RB2.2 UB1.5(SDA) UTL1.B14
UT2_PDCF: UTL2.B15
UT2_PDCS: UTL2.A15
UT2_PGDS: UTL2.A16
UT2_PGRD: UTL2.B16
UT2_URW00: UTL2.A01
UT2_URW01: UTL2.B02
UT2_URW02: UTL2.A03
UT2_URW03: UTL2.B03
UT2_URW04: UTL2.A04
UT2_URW05: UTL2.B05
UT2_URW06: UTL2.A06
UT2_UW07: UTL2.B06
UT2_UW08: UTL2.A07
UT2_UW09: UTL2.B08
UT2_UW10: UTL2.A09
UT2_UW11: UTL2.B10
UT2_UW12: UTL2.A11
UT2_UW13: UTL2.B12
UT2_UW14: UTL2.A13
UT2_UW15: UTL2.B14
UT3_PDCF: UTL3.B15
UT3_PDCS: UTL3.A15
UT3_PGDS: UTL3.A16
UT3_PGRD: UTL3.B16
UT3_URW00: UTL3.A01
UT3_URW01: UTL3.B02
UT3_URW02: UTL3.A03
UT3_URW03: UTL3.B03
UT3_URW04: UTL3.A04
UT3_URW05: UTL3.B05
UT3_URW06: UTL3.A06
UT3_UW07: UTL3.B06
UT3_UW08: UTL3.A07
UT3_UW09: UTL3.B08
UT3_UW10: UTL3.A09
UT3_UW11: UTL3.B10
UT3_UW12: UTL3.A11
UT3_UW13: UTL3.B12
UT3_UW14: UTL3.A13
UT3_UW15: UTL3.B14
N18382758: K10.4 R55.1 SW1.1
N18409210: K61.5 R22.1
N18409215: K61.6 R21.2
N18409217: K61.4 R20.1
N18409219: K61.3 R19.2
N18409246: K54.5 R14.1
N18409248: K54.6 R13.2
N18409250: K54.4 R12.1
N18409252: K54.3 R11.2
N18409257: K60.5 R18.1
N18409273: K60.3 R15.2
N18409275: K60.4 R16.1
N18409277: K60.6 R17.2
N18409282: K62.5 R26.1
N18409298: K62.3 R23.2
N18409300: K62.4 R24.1
N18409302: K62.6 R25.2
N18431358: C69.1 K55.5
N18431428: C70.1 K55.8
N18446682: C89.1 K56.5
N18446702: C90.1 K56.8
N18446941: C91.1 K57.5
N18446958: C92.1 K57.8
N18447198: C93.1 K58.5
N18447215: C94.1 K58.8
N18451749: C95.1 K59.5
N18451764: C96.1 K59.8
N18709887: C55.2 SW1.2
N18876028: K28.4 R147.1
N18876030: K28.5 R148.1
N18954388: K50.4 R184.1
N18954392: K50.5 R185.1
N21639620: R71.2 R163.2 U5.3(WP#)
N21639626: R72.2 U5.7(HOLD#)
N21654412: LDB1.1(A) LRB1.2

Not connected (* = marked no-connect by the designer): 038HX-887904K4Q-A100 1*; 980HX-887904-KAG- 1*; 261103AA031 1*; D101/D501 A1* A2* A3* A4* A5* A6* A7* A8* A9* A10* A11* A12* A13* A14* A15* A16* A17* B1* B2* B3* B4* B5* B6* B7* B8* B9* B10* B11* B12* B13* B14* B15* B16* B17* C1* C2* C3* C4* C5* C6* C7* C8* C9* C10* C11* C12* C13* C14* C15* C16* C17* D2* D3* D4* D5* D6* D7* D8* D9* D10* D11* D12* D13* D14* D15* D16*; D102/D502 A1* A2* A3* A4* A5* A6* A7* A8* A9* A10* A11* A12* A13* A14* A15* A16* A17* B1* B2* B3* B4* B5* B6* B7* B8* B9* B10* B11* B12* B13* B14* B15* B16* B17* C1* C2* C3* C4* C5* C6* C7* C8* C9* C10* C11* C12* C13* C14* C15* C16* C17* D2* D3* D4* D5* D6* D7* D8* D9* D10* D11* D12* D13* D14* D15* D16*; D103/D503 A1* A2* A3* A4* A5* A6* A7* A8* A9* A10* A11* A12* A13* A14* A15* A16* A17* B1* B2* B3* B4* B5* B6* B7* B8* B9* B10* B11* B12* B13* B14* B15* B16* B17* C1* C2* C3* C4* C5* C6* C7* C8* C9* C10* C11* C12* C13* C14* C15* C16* C17* D2* D3* D4* D5* D6* D7* D8* D9* D10* D11* D12* D13* D14* D15* D16*; D104 17* A17* B17*; D105/D505 A1* A2* A3* A4* A5* A6* A7* A8* A9* A10* A11* A12* A13* A14* A15* A16* A17* B1* B2* B3* B4* B5* B6* B7* B8* B9* B10* B11* B12* B13* B14* B15* B16* B17* C1* C2* C3* C4* C5* C6* C7* C8* C9* C10* C11* C12* C13* C14* C15* C16* C17* D2* D3* D4* D5* D6* D7* D8* D9* D10* D11* D12* D13* D14* D15* D16*; D106/D506 A1* A2* A3* A4* A5* A6* A7* A8* A9* A10* A11* A12* A13* A14* A15* A16* A17* B1* B2* B3* B4* B5* B6* B7* B8* B9* B10* B11* B12* B13* B14* B15* B16* B17* C1* C2* C3* C4* C5* C6* C7* C8* C9* C10* C11* C12* C13* C14* C15* C16* C17* D2* D3* D4* D5* D6* D7* D8* D9* D10* D11* D12* D13* D14* D15* D16*; D107/D507 A1* A2* A3* A4* A5* A6* A7* A8* A9* A10* A11* A12* A13* A14* A15* A16* A17* B1* B2* B3* B4* B5* B6* B7* B8* B9* B10* B11* B12* B13* B14* B15* B16* B17* C1* C2* C3* C4* C5* C6* C7* C8* C9* C10* C11* C12* C13* C14* C15* C16* C17* D2* D3* D4* D5* D6* D7* D8* D9* D10* D11* D12* D13* D14* D15* D16*; D108 17* A17* B17*; D109 17* A17* B17*; D110 17* A17* B17*; D111 17* A17* B17*; D112 17* A17* B17*; D113 17* A17* B17*; D114 17* A17* B17*; D115 17* A17* B17*; D116 17* A17* B17*; D117/D517 A1* A2* A3* A4* A5* A6* A7* A8* A9* A10* A11* A12* A13* A14* A15* A16* A17* B1* B2* B3* B4* B5* B6* B7* B8* B9* B10* B11* B12* B13* B14* B15* B16* B17* C1* C2* C3* C4* C5* C6* C7* C8* C9* C10* C11* C12* C13* C14* C15* C16* C17* D2* D3* D4* D5* D6* D7* D8* D9* D10* D11* D12* D13* D14* D15* D16*; D118/D518 A1* A2* A3* A4* A5* A6* A7* A8* A9* A10* A11* A12* A13* A14* A15* A16* A17* B1* B2* B3* B4* B5* B6* B7* B8* B9* B10* B11* B12* B13* B14* B15* B16* B17* C1* C2* C3* C4* C5* C6* C7* C8* C9* C10* C11* C12* C13* C14* C15* C16* C17* D2* D3* D4* D5* D6* D7* D8* D9* D10* D11* D12* D13* D14* D15* D16*; D119/D519 A1* A2* A3* A4* A5* A6* A7* A8* A9* A10* A11* A12* A13* A14* A15* A16* A17* B1* B2* B3* B4* B5* B6* B7* B8* B9* B10* B11* B12* B13* B14* B15* B16* B17* C1* C2* C3* C4* C5* C6* C7* C8* C9* C10* C11* C12* C13* C14* C15* C16* C17* D2* D3* D4* D5* D6* D7* D8* D9* D10* D11* D12* D13* D14* D15* D16*; D120 17* A17* B17*; D121/D521 A1* A2* A3* A4* A5* A6* A7* A8* A9* A10* A11* A12* A13* A14* A15* A16* A17* B1* B2* B3* B4* B5* B6* B7* B8* B9* B10* B11* B12* B13* B14* B15* B16* B17* C1* C2* C3* C4* C5* C6* C7* C8* C9* C10* C11* C12* C13* C14* C15* C16* C17* D2* D3* D4* D5* D6* D7* D8* D9* D10* D11* D12* D13* D14* D15* D16*; D122/D522 A1* A2* A3* A4* A5* A6* A7* A8* A9* A10* A11* A12* A13* A14* A15* A16* A17* B1* B2* B3* B4* B5* B6* B7* B8* B9* B10* B11* B12* B13* B14* B15* B16* B17* C1* C2* C3* C4* C5* C6* C7* C8* C9* C10* C11* C12* C13* C14* C15* C16* C17* D2* D3* D4* D5* D6* D7* D8* D9* D10* D11* D12* D13* D14* D15* D16*; D123/D523 A1* A2* A3* A4* A5* A6* A7* A8* A9* A10* A11* A12* A13* A14* A15* A16* A17* B1* B2* B3* B4* B5* B6* B7* B8* B9* B10* B11* B12* B13* B14* B15* B16* B17* C1* C2* C3* C4* C5* C6* C7* C8* C9* C10* C11* C12* C13* C14* C15* C16* C17* D2* D3* D4* D5* D6* D7* D8* D9* D10* D11* D12* D13* D14* D15* D16*; D124 17* A17* B17*; D301 17* A17* B17*; D302 17* A17* B17*; D305 17* A17* B17*; D306 17* A17* B17*; D317 17* A17* B17*; D318 17* A17* B17*; D321 17* A17* B17*; D322 17* A17* B17*; DPS1 A04* A08* A10* A14* B04* B08* B10* B14* C04* C08* C10* C14*; DPS2 A04* A08* A10* A14* B04* B08* B10* B14* C04* C08* C10* C14*; DPS3 A04* A08* A10* A14* B04* B08* B10* B14* C04* C08* C10* C14*; HX8879-F04 1*; K10 2* 5* 6* 7*; K28 2* 7*; K48 5* 6* 7*; K50 2* 7*; K54 2* 7*; K55 3* 10*; K56 3* 10*; K57 3* 10*; K58 3* 10*; K59 3* 10*; K60 2* 7*; K61 2* 7*; K62 2* 7*; LOGO1 1*; LOGO2 1*; SCREW1 1* 2* 3* 4* 5* 6* 7* 8* 9* 10* 11* 12* 13* 14* 15* 16* 17* 18* 19* 20* 21* 22* 23* 24* 25* 26* 27* 28* 29* 30* 31* 32* GH1* GH2* GH3* GH4*; SITE1 NGH1* NGH2* NGH3* NGH4* NUT1* NUT2* NUT3* NUT4*; UF1 1*; UTL1 A17* B17*; UTL2 A17* B17*; UTL3 A17* B17*; WFBGA-10X3.5X0.636-P0.65 1*

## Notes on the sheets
sheet 10
- V93K FULL SIZE
- TOP VIEW
- DPS7
- UTILITY8
- DPS8
- UTILITY4
- DPS2
- UTILITY3
- DPS6
- DPS6
- UTILITY7
- D424
- D420
- D432
- D428
- D316
- D312
- D416
- D412
- D224
- D220
- D232
- D228
- D116
- PS1600
- D112
- PS1600
- D216
- D212
- D423
- D419
- D431
- MBAV8
- D427
- D315
- D311
- D415
- D411
- D223
- D219
- D231
- MBAV9
- D227
- D115
- PS1600
- D111
- PS1600
- D215
- D211
- D422
- D418
- D430
- D426
- D314
- D310
- D414
- D410
- D222
- D218
- D230
- D226
- D114
- PS1600
- D110
- PS1600
- D214
- D210
- D421
- D417
- D429
- DPS64
- D425
- DPS64
- D313
- D309
- D413
- D409
- D221
- D217
- D229
- DPS64
- D225
- DPS64
- D113
- PS1600
- D109
- PS1600
- D213
- D209
- GROUP 7
- GROUP 8
- GROUP 2
- GROUP 6
- 140 MM
- M5 PEM NUT
- M5 PEM NUT
- HX8879-F04
  One Site Channel
- All of Channel
- RX: 8
- PS9G :128
- 40mm
- TX:16
- Change kit
- PS1600:320
- Channel:41
- PIN1
- PIN1
- PIN1
- PIN1
- DPS:64
- 140 MM
- Site1
- Site2
- Site3
- Site4
- AUX:4
- HX8879-F04
- HX8879-F04
- HX8879-F04
- HX8879-F04
- UTILITY:128
- BGA75
- BGA75
- BGA75
- BGA75
- DPS:13+1(MERGE)
- Relay: 16
- M5 PEM NUT
- M5 PEM NUT
- GROUP 4
- GROUP 3
- GROUP 1
- GROUP 5
- D125
- PS1600
- D129
- PS1600
- D117
- PS1600
- D121
- PS1600
- D101
- PS1600
- D105
- PS1600
- D201
- D205
- D325
- D329
- D317
- PS9G
- D321
- PS9G
- D301
- PS9G
- D305
- PS9G
- D401
- D405
- D126
- PS1600
- D130
- PS1600
- D118
- PS1600
- D122
- PS1600
- D102
- PS1600
- D106
- PS1600
- D202
- D206
- D326
- D330
- D318
- PS9G
- D322
- PS9G
- D302
- PS9G
- D306
- PS9G
- D402
- D406
- D127
- PS1600
- D131
- PS1600
- D119
- PS1600
- D123
- PS1600
- D103
- PS1600
- D107
- PS1600
- D203
- D207
- D327
- D331
- D319
- D323
- D303
- D307
- D403
- D407
- D128
- PS1600
- D132
- PS1600
- D120
- PS1600
- D124
- PS1600
- D104
- PS1600
- D108
- PS1600
- D204
- D208
- D328
- D332
- D320
- D324
- D304
- D308
- D404
- D408
- UTILITY5
- DPS4
- UTILITY1
- DPS3
- UTILITY2
- DPS1
- UTILITY6
- DPS5
- DPS5
- Socket M3 Nut 4*4=16
- Socket Drawing Follow:
- Ball Out Follow:
- POD Follow:
- Operating temp : -40~+105
sheet 11
- History
- 2026 11/2 -->
- Modify TX to 2.7Gbps
  Removed the relay from the Peripheral  circuit
  Keep 0402 package for NC CAP
  Spare Relay Remove
  J1 utilizes a DIP switch for switching
- 2026 11/3 -->
- Modify SPI VCC to EEPROM Flash VCC
- 2026 11/4 -->
- 1.	Remove K12/K13/K29/K30 pull-up Relays
  2.	Remove TEST K49 pull-up relay
  3.	Remove  AUX K50 Pull-down relay
  4.	Remove EEPROM circuit, retain K28 only.
  5.	Flash uses Flash Sockets
  6.	Power  - marked current <200mA, and VDD09_CORE is < 2A
  7.	VDD09_CORE merge 2 CSDPS Channel
  8.	Modify EEPROM Flash VCC to Flasher VCC
- 2026 11/5 -->
- 1.	Pin Follow EVB
  2.	Remove R199
  3.	Modify Flash_VCC to VCC_I2C_Flash_18
  4.	Change C14 pin name from VDDRX_AUX to VDDRX_AUX_09
  5.	Modify to retain AUX K50
  6.REMOVE R183
sheet 12
- ISP TX 2.7Gbps
- EDP RX 5.4Gbps
- ISP TX 2.7Gbps
- DIFF 85 Ohm
- DIFF 100 Ohm
- Swap P/N (P=+, N=-) to prevent RX routing from impacting trace length
  IC PIN - RX_P0 connected to Test Channel - 85DCH-
  IC PIN - RX_N0 connected toTest Channel - 85DCH+
  IC PIN - RX_P1 connected to Test Channel - 85DCH-
  IC PIN - RX_N1 connected to Test Channel - 85DCH+
  IC PIN - RX_P2 connected to Test Channel - 85DCH-
  IC PIN - RX_N2 connected to Test Channel - 85DCH+
  IC PIN - RX_P3 connected to Test Channel - 85DCH-
  IC PIN - RX_N3 connected to Test Channel - 85DCH+
- TEST
- AUX
- DIFF 100 Ohm
- Close to DUT
- Close to DUT
- Close to Base
- DIFF 100 Ohm
- DIFF 100 Ohm
- The DUT~CH trace width 20 mil
- RST
- 2026 11/2  jumper to DIP switch
sheet 13
- FLASH
- Flash uses MX25U4035FM1I-SOP8
- ¡°Please note that Flash uses the shortest path
  and all sites have the same length.
  **Line length < 4000MIL
- I2C
sheet 14
- CAP Reference :
  CD*-->Place on TOP¡Fclose to PIN
  CC*-->Place on TOP¡Fclose to PIN
  CA*-->Place on TOP¡Fclose to ATE
- RLY close to ATE
  C*--> Place on Bot ; Close RELAY
- <2A
- PIN
- C4
  C8
  C9
  C10
- <200mA
- PIN
- C5
  C6
  C11
- <200mA
- PIN
- A5
- <200mA
- PIN
- C7
- <200mA
- PIN
- A4
- <200mA
- PIN
- C14
- <200mA
- PIN
- E15
- <200mA
- PIN
- B3
- <200mA
- PIN
- B14
- <200mA
- PIN
- C3
sheet 15
- CAP Reference :
  CD*-->Place on TOP¡Fclose to PIN
  CC*-->Place on TOP¡Fclose to PIN
  CA*-->Place on TOP¡Fclose to ATE
sheet 16
- Support Circuits
- DPS Trigger & VBump
- 0.1uF
- 10K£[
- 10K£[
- All UT_5V Merge
- MCB_CT1
- MCB_CT2
sheet 17
- GROUP1
- D105
- D305
- D106
- D306
- D107
- D307
- D108
- D308
- GPDPS:GND
- GPDPS:FORCE
- GPDPS:FORCE
- GPDPS:GND
- GPDPS:FORCE
- GPDPS:FORCE
- GPDPS:GND
- GPDPS:FORCE
- GPDPS:FORCE
- GPDPS:GND
- GPDPS:FORCE
- GPDPS:FORCE
- D101
- D301
- D102
- D302
- D103
- D303
- D104
- D304
sheet 18
- D313
- GROUP2
- D113
- D114
- D314
- D115
- D315
- D116
- D316
- D313
- GPDPS:GND
- GPDPS:FORCE
- GPDPS:FORCE
- GPDPS:GND
- GPDPS:FORCE
- GPDPS:FORCE
- GPDPS:GND
- GPDPS:FORCE
- GPDPS:FORCE
- GPDPS:GND
- GPDPS:FORCE
- GPDPS:FORCE
- D109
- D110
- D310
- D111
- D311
- D112
- D312
- D309
- V93000 GROUP1
- VY22520
- V93000 GROUP1
- VY22520
sheet 19
- GROUP3
- PS RF FE2
- PS RF FE1
- D121
- D321
- D122
- D322
- D123
- D323
- D124
- D324
- GPDPS:GND
- GPDPS:FORCE
- GPDPS:FORCE
- GPDPS:GND
- GPDPS:FORCE
- GPDPS:FORCE
- GPDPS:GND
- GPDPS:FORCE
- GPDPS:FORCE
- GPDPS:GND
- GPDPS:FORCE
- GPDPS:FORCE
- PS RF SRC-1-2
- PS RF SRC-3-4
- D117
- D317
- D118
- D318
- D119
- D319
- D120
- D320
- EEPROM
- V93000 GROUP1
- VY22520
